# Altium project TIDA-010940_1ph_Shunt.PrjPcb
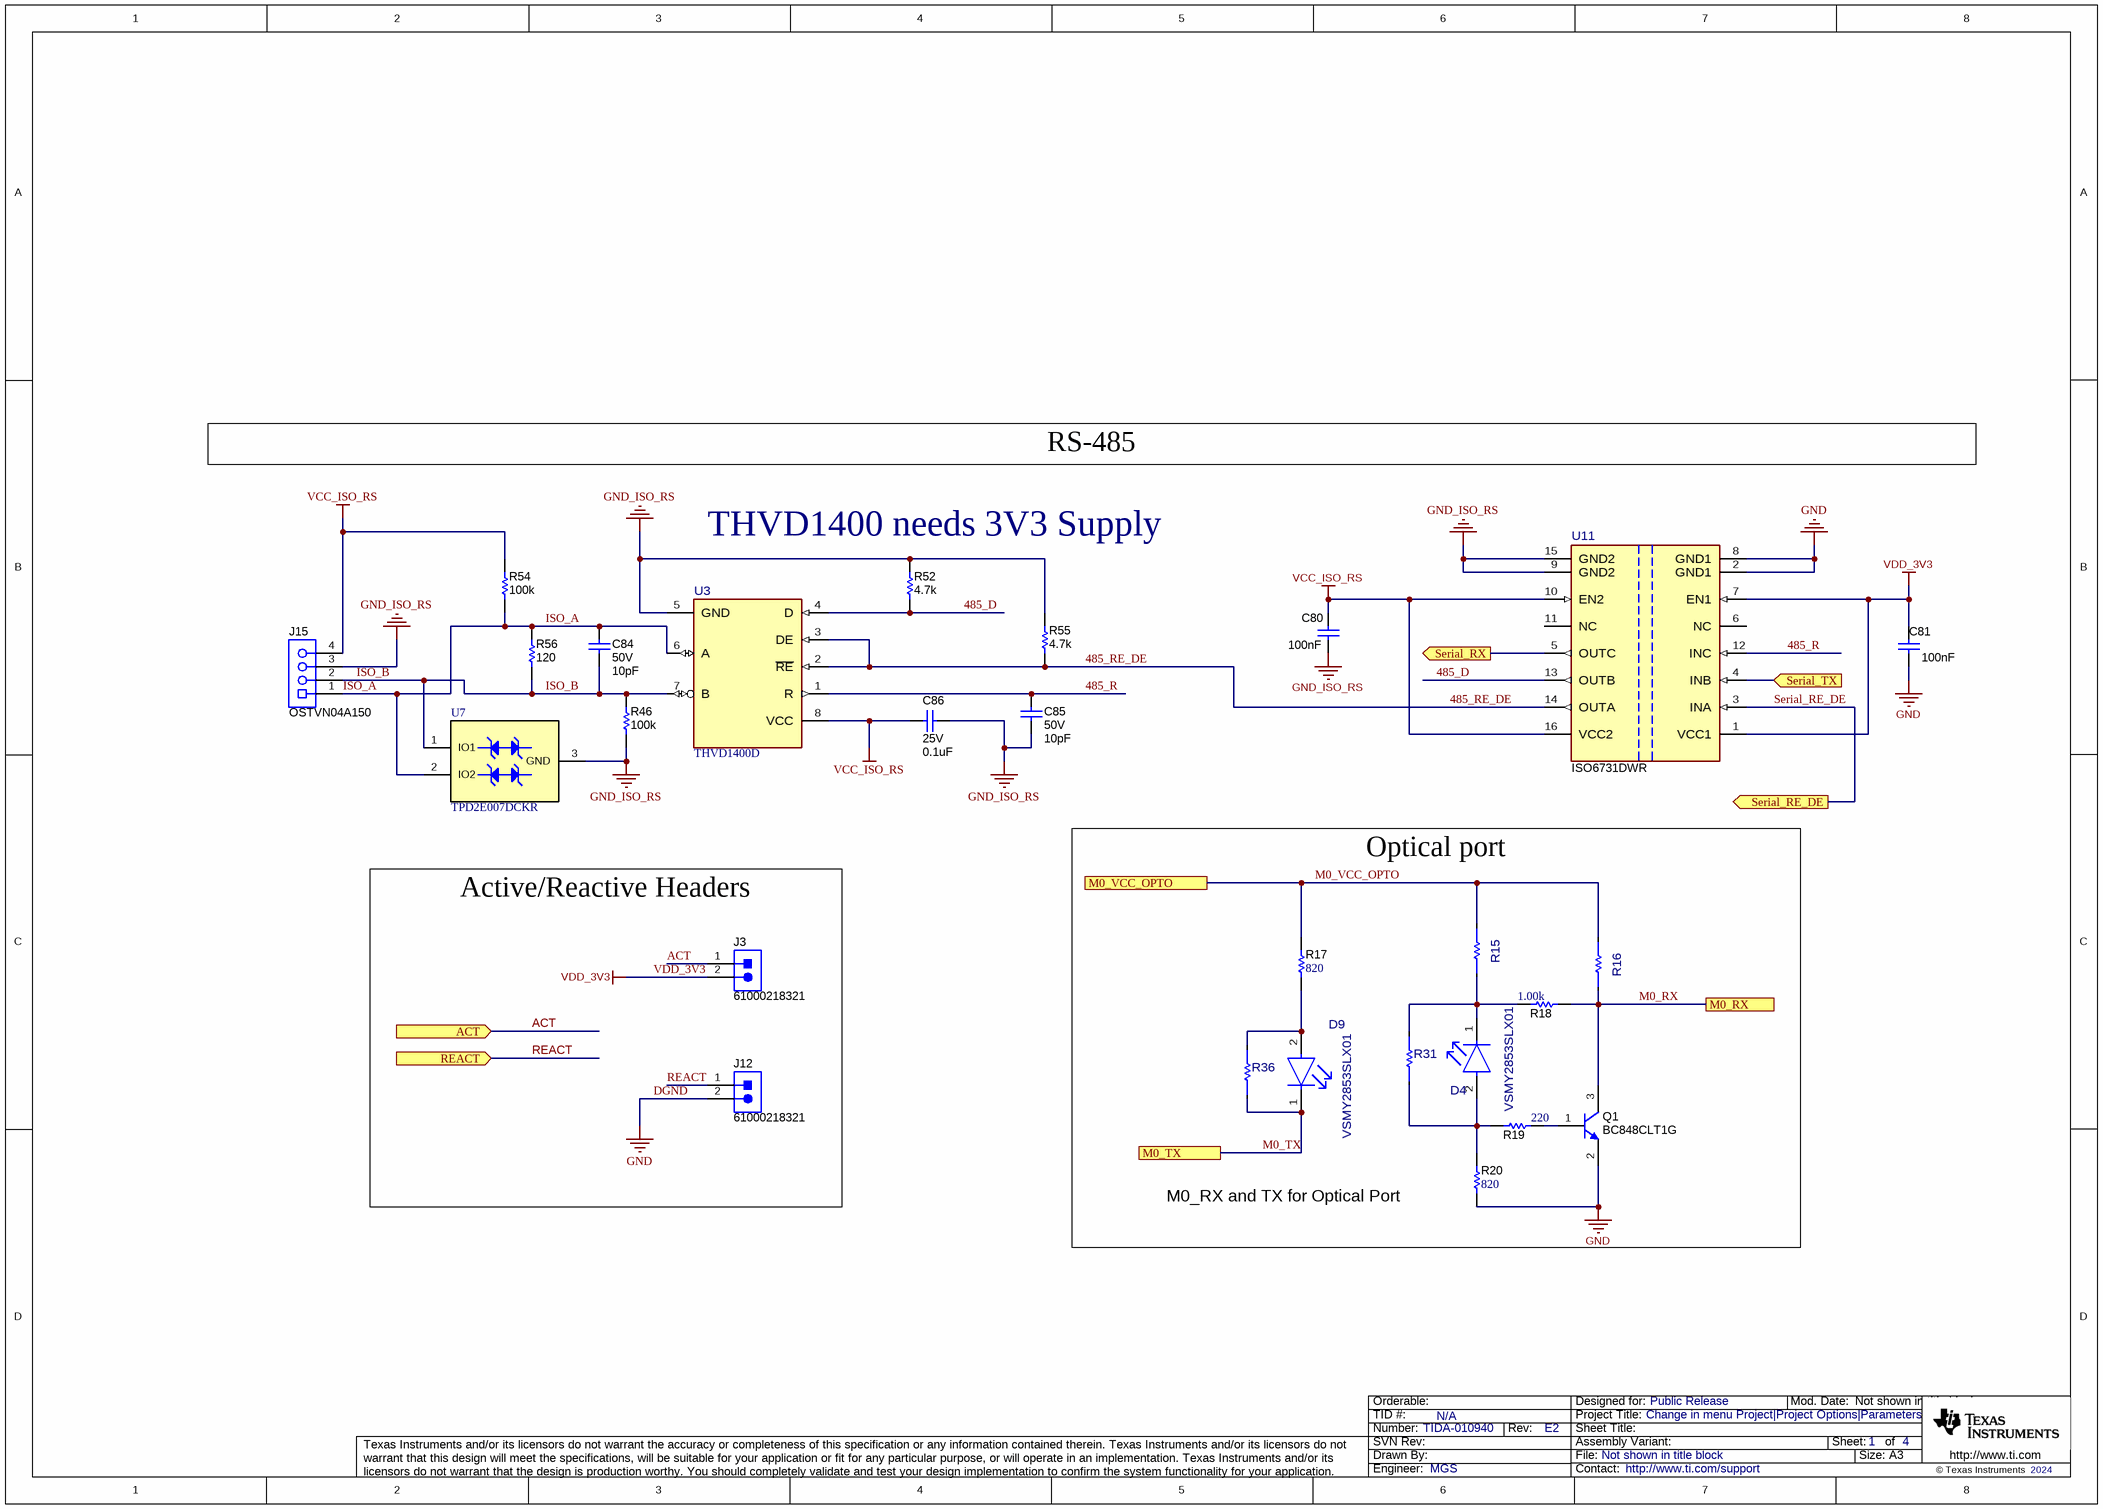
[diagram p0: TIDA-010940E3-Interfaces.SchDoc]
a0797195: Who did the Layout?; CopyrightYear: 2024; PCB_Rev: E3; PRJ_Customer: Public Release; PRJ_Engineer: MGS; PRJ_Number: TIDA-010940; PRJ_Title: Change in menu Project|Project Options|Parameters; SCH_Rev: E2; TechSupport: http://www.ti.com/support; TID: N/A
4 sheets, 137 parts. Net scope: global (net labels, ports and power ports of the same name join across sheets).
Board file: TIDA-010940E3.PcbDoc
Sheets:
  TIDA-010940E3-Interfaces.SchDoc
  TIDA-010940E3-Hardware.SchDoc
  TIDA-010940E3-1P_ADS131M03.SchDoc
  TIDA-010940E3-M0L228_80p.SchDoc

## Sheet TIDA-010940E3-Interfaces.SchDoc
size A3; Date: Not shown in title block; ApprovedBy: Not shown in title block; CheckedBy: Not shown in title block; Author: Not shown in title block; CompanyName: Not shown in title block; Engineer: Not shown in title block; Organization: Not shown in title block; Address1: Not shown in title block; Address2: Not shown in title block; Address3: Not shown in title block; Address4: Not shown in title block; DocumentNumber: 1; Revision: Use project parameter SCH_Rev; SheetNumber: 1; SheetTotal: 4; PageSetup: Record=PageOptions¦CenterHorizontal=True¦CenterVertical=True¦PrintScale=0.69¦XCorrection=1.00¦YCorrection=1.00¦PrintKind=0¦BorderSize=5000000¦LeftOffset=0¦BottomOffset=0¦Orientation=2¦PaperLength=1000¦PaperWidth=1000¦Scale=100¦PaperSource=15¦PrintQuality=600¦MediaType=1¦DitherType=10¦PaperKind=Letter¦PrintScaleMode=1

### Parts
C80  Cap_F: 100nF  [0603]  (hidden comment: C0603X104K3RACTU)
C81  Cap_F: 100nF  [0603]  (hidden comment: C0603X104K3RACTU)
C84  VDC_V: 50V  ValueDisplayed: 10pF  [0603]  (hidden comment: CGA3E2C0G1H100D080AA)
C85  VDC_V: 50V  ValueDisplayed: 10pF  [0603]  (hidden comment: CGA3E2C0G1H100D080AA)
C86  VDC_V: 25V  ValueDisplayed: 0.1uF  [0603]  (hidden comment: CGA3E2X8R1E104K080AA)
D4  VSMY2853SLX01  [FP-VSMY2853SLX01_SMT_LED_2MM30_2MM55-MFG]
D9  VSMY2853SLX01  [FP-VSMY2853SLX01_SMT_LED_2MM30_2MM55-MFG]
J3  61000218321  [Wurth_61000218321]
J12  61000218321  [Wurth_61000218321]
J15  OSTVN04A150  [On-Shore_OSTVN04A150]
Q1  BC848CLT1G  [SOT-23]
R15  CR0402-10W-000T  [FP-CR0402-10W-000T_0402-MFG]  (value not drawn)
R16  ERA-2ARB8061X  [FP-ERA-2ARB8061X_0402-MFG]  (value not drawn)
R17  ValueDisplayed: 820  [0402]  (hidden comment: RC0402FR-07820RL)
R18  ValueDisplayed: 1.00k  [0402]  (hidden comment: RC0402FR-071KL)
R19  ValueDisplayed: 220  [0402]  (hidden comment: ERJ-2RKF2200X)
R20  ValueDisplayed: 820  [0402]  (hidden comment: CRCW0402820RJNED)
R31  PMR18EZPJ000  [FP-PMR18EZPJ000_1206-MFG]  (value not drawn)
R36  PMR18EZPJ000  [FP-PMR18EZPJ000_1206-MFG]  (value not drawn)
R46  ValueDisplayed: 100k  [0603]  (hidden comment: CRCW0603100KJNEA)
R52  ValueDisplayed: 4.7k  [0603]  (hidden comment: CRCW06034K70JNEA)
R54  ValueDisplayed: 100k  [0603]  (hidden comment: CRCW0603100KJNEA)
R55  ValueDisplayed: 4.7k  [0603]  (hidden comment: CRCW06034K70JNEA)
R56  ValueDisplayed: 120  [0603]  (hidden comment: RT0603DRE07120RL)
U3  THVD1400D  [D0008B-MFG]
U7  TPD2E007DCKR  [DCK0003A_L]
U11  ISO6731DWR  [DW0016A-MFG]

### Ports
ACT (in), M0_RX, M0_TX, M0_VCC_OPTO, REACT (in), Serial_RE_DE (out), Serial_RX (out), Serial_TX (in)

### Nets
DGND: C81.2 J12.2 Q1.2(E) R20.1 U11.2(GND1) U11.8(GND1)  [also labelled GND]
GND_ISO_RS: C80.2 C85.1 C86.2 J15.3 R46.1 R52.2 R55.2 U3.5(GND) U7.3(GND) U11.9(GND2) U11.15(GND2)
VCC_ISO_RS: C80.1 C86.1 J15.4 R54.2 U3.8(VCC) U11.10(EN2) U11.16(VCC2)
VDD_3V3: C81.1 J3.2 U11.1(VCC1) U11.7(EN1)  [project net DVDD]
485_D: R52.1 U3.4(D) U11.13(OUTB)
485_R: C85.2 U3.1(R) U11.12(INC)
485_RE_DE: R55.1 U3.2(~{RE}) U3.3(DE) U11.14(OUTA)
ACT: J3.1 ; port ACT
ISO_A: C84.1 J15.1 R54.1 R56.2 U3.6(A) U7.2(IO2)
ISO_B: C84.2 J15.2 R46.2 R56.1 U3.7(B) U7.1(IO1)
M0_RX: Q1.3(C) R16.1 R18.1 ; port M0_RX
M0_TX: D9.1(Cathode) R36.1 ; port M0_TX
M0_VCC_OPTO: R15.2 R16.2 R17.2 ; port M0_VCC_OPTO
REACT: J12.1 ; port REACT
Serial_RE_DE: U11.3(INA) ; port Serial_RE_DE
Serial_RX: U11.5(OUTC) ; port Serial_RX
Serial_TX: U11.4(INB) ; port Serial_TX
NetD4_1: D4.1(Cathode) R15.1 R18.2 R31.2
NetD4_2: D4.2(Anode) R19.2 R20.2 R31.1
NetD9_2: D9.2(Anode) R17.1 R36.2
NetQ1_1: Q1.1(B) R19.1

Not connected (* = marked no-connect by the designer): U11 6(NC) 11(NC)

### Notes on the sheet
- RS-485
- (near R52) THVD1400 needs 3V3 Supply
- Active/Reactive Headers
- Optical port
- M0_RX and TX for Optical Port

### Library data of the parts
C80 C81 = CMP-0006979-5: CAP, CERM, 0.1 uF, 25 V, +/- 10%, X7R, 0603; Manufacturer: Kemet; TaMin_C: -55°C; Polarized: N; SizeAreaWB_mm2: 4.68; Value1: Unknown; U/M: EA; Value: 0.1uF; TaMax_C: 125°C; SizeZ_mm: 1; SizeX_mm: 1.6; SizeY_mm: 0.8; Value2: 25V; SizeArea_mm2: 1.28; AEC Category: Q200
C84 C85 = CMP-0007069-4: CAP, CERM, 10 pF, 50 V, +/- 5%, C0G/NP0, AEC-Q200 Grade 1, 0603; Manufacturer: TDK; TaMin_C: -55°C; Polarized: N; SizeAreaWB_mm2: 4.68; Value1: Unknown; U/M: EA; Value: 10pF; TaMax_C: 125°C; SizeZ_mm: 1; SizeX_mm: 1.6; SizeY_mm: 0.8; SizeArea_mm2: 1.28; AEC Qualified: Y; AEC Category: Q200
C86 = CMP-0007090-4: CAP, CERM, 0.1 uF, 25 V, +/- 10%, X8R, AEC-Q200 Grade 0, 0603; Manufacturer: TDK; TaMin_C: -55°C; Polarized: N; SizeAreaWB_mm2: 4.68; Value1: Unknown; U/M: EA; Value: 0.1uF; TaMax_C: 150°C; SizeZ_mm: 1; SizeX_mm: 1.6; SizeY_mm: 0.8; SizeArea_mm2: 1.28; CompType: Capacitor; AEC Qualified: Y; Cap_F: 100nF; AEC Grade: 0; AEC Category: Q200
D4 D9 = CMP-0120648-1: IR Emitter High Speed 850nm 50mW/sr 100mA 1.9V 2-Pin SMD T/R; Manufacturer: Vishay; Color: Infrared; Tjmax_C: 100°C; Vf_V: 1.6V; Angle: 56°; Power_TotalModule: 190mW; SizeZ_mm: 2.5mm; Vr_V: 5V; AEC Grade: Grade 3; AEC Qualified: Yes; Led Orientation: Side View; TaMax_C: +85°C; TaMin_C: -40°C
J3 J12 = CMP-0054787-1: Header, 2.54mm, 2x1, Gold, SMT; Manufacturer: Wurth Elektronik; CNHeader: TRUE; Shrouded: N; Gender: Male; Row_Count: 1; Pitch_mm: 2.54; CT: FALSE
J15 = CMP-0075095-1: Terminal Block, 2.54mm, 4x1, Brass, TH; Manufacturer: On-Shore Technology; CT: True; CNHeader: False
Q1 = CMP-0000377-2: Transistor, NPN, 30 V, 0.1 A, SOT-23; Manufacturer: ON Semiconductor; TaMax_C: 150°C; Value2: 800; Value1: 0.1 A; Vcesat1_V: 700mV; SizeX_mm: 2.5; SizeY_mm: 3; TaMin_C: -55°C; IcRated_A: 100mA; CompType: BJT; SizeZ_mm: 1.1; Value: 30 V; SizeArea_mm2: 7.5; NPN: 1; Vceo_V: 30V; PNP: 0; AEC Category: Q101; SizeAreaWB_mm2: 14; U/M: EA
R15 = CMP-0094948-1: 0 Ohms Jumper 0.1W, 1/10W Chip Resistor 0402 (1005 Metric) - Thick Film; Manufacturer: Venkel; Value: 0uΩ; Res_ohm: 0; SizeZ_mm: 0.4mm; AEC Qualified: No; VDC_V: 50V; Power_W: 100mW
R16 = CMP-0121809-1: 8.06 kOhms ±0.1% 0.063W, 1/16W Chip Resistor 0402 (1005 Metric) Automotive AEC-Q200 Thin Film; Manufacturer: Panasonic; Power_W: 63mW; TempCo: 10ppm/°C; Value: 8.06k; SizeZ_mm: 0.4mm; AEC Qualified: Yes; VDC_V: 50V; AEC Grade: Grade 1
R17 = CMP-0026743-1: RES, 820, 1%, 0.063 W, 0402; Manufacturer: Yageo America; Power_W: 63mW; TempCo: 100 ppm/C; Value_Code: 820R; Value: 820; SizeX_mm: 1; SizeY_mm: 0.5; SizeZ_mm: 0.6; Value2: 0.063W; AEC Qualified: N; VDC_V: 50V; AEC Category: Q200; U/M: EA
R18 = CMP-0026725-1: RES, 1.00 k, 1%, 0.0625 W, 0402; Manufacturer: Yageo America; Power_W: 62.5mW; TempCo: 100 ppm/C; Value_Code: 1k00; Value: 1.00k; EIA_Code: E96; Res_ohm: 1k; SizeX_mm: 1; SizeY_mm: 0.5; SizeZ_mm: 0.6; AEC Qualified: N; VDC_V: 50V; AEC Category: Q200; U/M: EA
R19 = CMP-0026680-1: RES, 220, 1%, 0.1 W, AEC-Q200 Grade 0, 0402; Manufacturer: Panasonic; Power_W: 100mW; TempCo: 100 ppm/C; Value_Code: 220R; Value: 220; SizeX_mm: 1; SizeY_mm: 0.5; SizeZ_mm: 0.6; Value2: 0.1W; AEC Qualified: Y; VDC_V: 50V; AEC Category: Q200; AEC Grade: 0; U/M: EA
R20 = CMP-0026979-3: RES, 820, 5%, 0.063 W, AEC-Q200 Grade 0, 0402; Manufacturer: Vishay-Dale; Power_W: 63mW; TempCo: 200 ppm/C; Value_Code: 820R; Value: 820; EIA_Code: E24; SizeX_mm: 1; SizeY_mm: 0.5; SizeZ_mm: 0.6; Value2: 0.063W; AEC Qualified: Y; VDC_V: 50V; AEC Category: Q200; AEC Grade: 0
R31 R36 = CMP-0093507-1: 0 Ohms Jumper 1W Chip Resistor 1206 (3216 Metric) Automotive AEC-Q200, Current Sense Thick Film; Manufacturer: Rohm Semiconductor; SizeZ_mm: 0.42mm; AEC Grade: Grade 0; Value: 0; AEC Qualified: Yes; Max Current: 38.7A
R46 R54 = CMP-0025698-4: RES, 100 k, 5%, 0.1 W, AEC-Q200 Grade 0, 0603; Manufacturer: Vishay-Dale; Power_W: 100mW; TempCo: 200 ppm/C; Value: 100k; EIA_Code: E24; SizeX_mm: 1.6; SizeY_mm: 0.8; SizeZ_mm: 1; Value2: 0.1W; SizeArea_mm2: 1.28; AEC Qualified: Y; VDC_V: 75V; AEC Category: Q200; AEC Grade: 0
R52 R55 = CMP-0025817-4: RES, 4.7 k, 5%, 0.1 W, AEC-Q200 Grade 0, 0603; Manufacturer: Vishay-Dale; Power_W: 100mW; TempCo: 200 ppm/C; Value_Code: 4k70; Value: 4.7k; EIA_Code: E24; SizeX_mm: 1.6; SizeY_mm: 0.8; SizeZ_mm: 1; Value2: 0.1W; SizeArea_mm2: 1.28; AEC Qualified: Y; VDC_V: 75V; AEC Category: Q200; AEC Grade: 0
R56 = CMP-0024624-2: RES, 120, 0.5%, 0.1 W, 0603; Manufacturer: Yageo America; Power_W: 100mW; TempCo: 50 ppm/C; Value_Code: 120R; U/M: EA; Value: 120; EIA_Code: E192; SizeX_mm: 1.6; SizeY_mm: 0.8; SizeZ_mm: 1; Value2: 0.1W; SizeArea_mm2: 1.28; VDC_V: 75V; AEC Category: Q200
U3 = CMP-0089978-1: 500 kbps RS-485 Transceivers With ±8-kV IEC ESD Protection; Manufacturer: Texas Instruments; Interface: RS-485,RS-422; SizeZ_mm: 1.75mm; Number Of Receivers: 1; TaMax_C: +125°C; TJmax_C: +150°C; Min Supply Voltage: 4.5V; Nominal Supply Current: 275-440uA; Simplex Duplex: Half-Duplex; Standoff Height: 0.11mm; Max Supply Voltage: 5.5V; TaMin_C: -40°C; Data Rate: 500kbits/s; AEC Qualified: No
U7 = CMP-0043100-2: ESD Protection Array for AC Signal Data Interface, 2 Channels, -40 to +85 degC, 3-pin SC70 (DCK), Green (RoHS & no Sb/Br); Manufacturer: Texas Instruments; IO Leakage Current(nA): 50; IEC 61000-4-2 Contact(+/- kV): 8; IO Capacitance(Typ)(pF): 15; Breakdown Voltage(Min)(V): +/-14; SubFamily: ESD Solution; AEC Category: Q200; AEC Qualified: N; CompType: IC; SizeAreaWB_mm2: 9.3; SizeArea_mm2: 4.2; SizeX_mm: 2.1; SizeY_mm: 2; SizeZ_mm: 1.1
U11 = CMP-0094636-1: Manufacturer: Texas Instruments; Min Supply Voltage: 1.71V; TJmax_C: +150°C; Max Supply Voltage: 5.5V; Standoff Height: 0.1mm; TaMax_C: +125°C; SizeZ_mm: 2.65mm; Interface: SPI,CAN,RS-232,RS-485; TaMin_C: -40°C; AEC Qualified: No

## Sheet TIDA-010940E3-Hardware.SchDoc
size 431 x 279 mm; Date: Not shown in title block; ApprovedBy: Not shown in title block; CheckedBy: Not shown in title block; Author: Not shown in title block; CompanyName: Not shown in title block; Engineer: Not shown in title block; Organization: Not shown in title block; Address1: Not shown in title block; Address2: Not shown in title block; Address3: Not shown in title block; Address4: Not shown in title block; DocumentNumber: 3; Revision: Use project parameter SCH_Rev; SheetNumber: 2; SheetTotal: 4; PageSetup: Record=PageOptions¦CenterHorizontal=True¦CenterVertical=True¦PrintScale=1.00¦XCorrection=1.00¦YCorrection=1.00¦PrintKind=0¦BorderSize=5000000¦LeftOffset=0¦BottomOffset=0¦Orientation=2¦PaperLength=1000¦PaperWidth=1000¦Scale=100¦PaperSource=15¦PrintQuality=600¦MediaType=1¦DitherType=10¦PaperKind=Letter¦PrintScaleMode=1
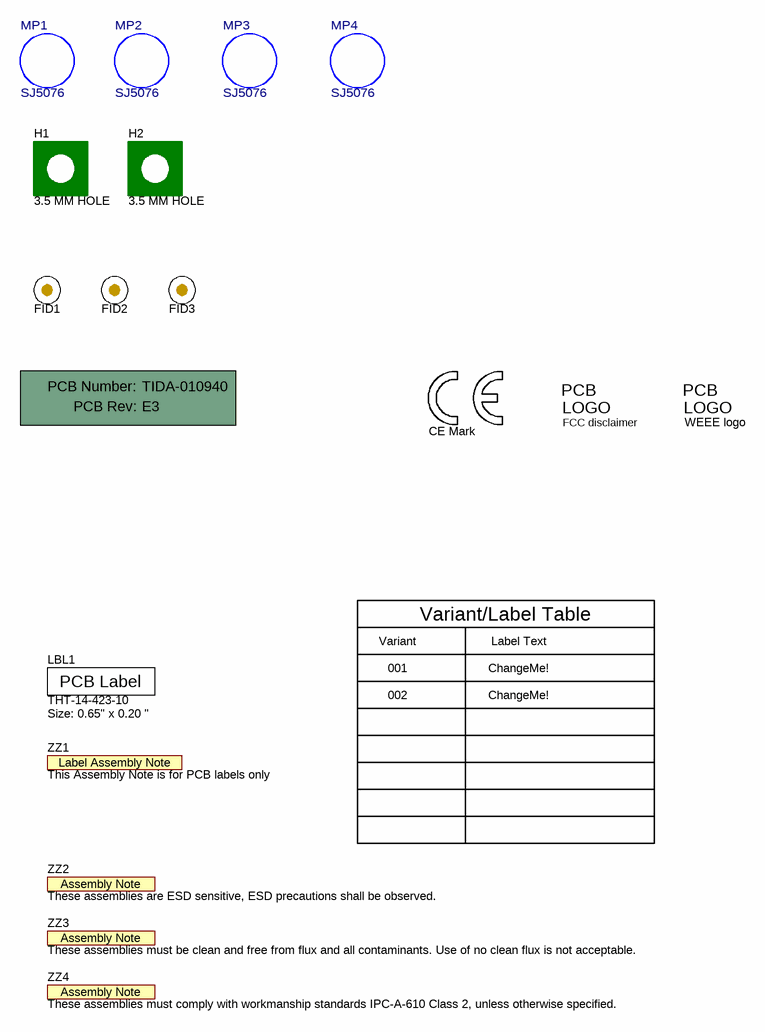
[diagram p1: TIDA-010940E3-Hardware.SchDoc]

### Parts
!PCB  Printed Circuit Board  (value not drawn)  (mechanical)
FID1  Fiducial  [Fiducial10-20]  (value not drawn)
FID2  Fiducial  [Fiducial10-20]  (value not drawn)
FID3  Fiducial  [Fiducial10-20]  (value not drawn)
H1  3.5 MM HOLE  [3_5MM_HOLE]
H2  3.5 MM HOLE  [3_5MM_HOLE]
LBL1  THT-14-423-10  Note: Size: 0.65" x 0.20 "  [Label_650x200]
Logo2  CE Mark  [CE_Mark_5mm]  (no BOM)
Logo3  FCC disclaimer  [FCC_disclaimer]  (no BOM)
Logo4  WEEE logo  [WEEE_Minimum]  (no BOM)
MP1  SJ5076  [FP-SJ5076_BUMPER_CYLIN-MFG]
MP2  SJ5076  [FP-SJ5076_BUMPER_CYLIN-MFG]
MP3  SJ5076  [FP-SJ5076_BUMPER_CYLIN-MFG]
MP4  SJ5076  [FP-SJ5076_BUMPER_CYLIN-MFG]
ZZ1  This Assembly Note is for PCB labels only  [AssemblyNoteLabel]  (no BOM)
ZZ2  These assemblies are ESD sensitive, ESD precautions shall be observed.  [AssemblyNote]  (no BOM)
ZZ3  These assemblies must be clean and free from flux and all contaminants. Use of no clean flux is not acceptable.  [AssemblyNote]  (no BOM)
ZZ4  These assemblies must comply with workmanship standards IPC-A-610 Class 2, unless otherwise specified.  [AssemblyNote]  (no BOM)

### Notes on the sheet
- Variant
- Variant/Label Table
- Label Text
- 001
- 002
- ChangeMe!

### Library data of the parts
!PCB = CMP-0003618-2: Manufacturer: Any; PartNumber: TIDA-010940
FID1-FID3 = CMP-0077181-1: Fiducial mark.  There is nothing to buy or mount.
H1 H2 = CMP-0079299-1: 3.5 mm PCB Hole; Manufacturer: Any; CompType: Pad
LBL1 = CMP-0003625-1: Thermal Transfer Printable Labels, 0.650" W x 0.200" H - 10,000 per roll; Manufacturer: Brady; CompType: Label
Logo2 = CMP-0074844-1: SymbolCreator: a0412235
Logo3 = CMP-0074847-1: FCC_disclaimer; Library Reference: Logo
Logo4 = CMP-0074769-1
MP1-MP4 = CMP-0097139-1: Bumper Cylindrical, Flat Top 0.315" Dia (8.00mm) Polyurethane Black; Manufacturer: 3M; SizeZ_mm: 3.3mm; AEC Qualified: No
ZZ1 = CMP-0003616-3
ZZ2 = CMP-0077236-1
ZZ3 = CMP-0077237-1
ZZ4 = CMP-0077238-1

## Sheet TIDA-010940E3-1P_ADS131M03.SchDoc
size 431 x 279 mm; Date: Not shown in title block; ApprovedBy: Not shown in title block; CheckedBy: Not shown in title block; Author: Not shown in title block; CompanyName: Not shown in title block; Engineer: Not shown in title block; Organization: Not shown in title block; Address1: Not shown in title block; Address2: Not shown in title block; Address3: Not shown in title block; Address4: Not shown in title block; DocumentNumber: 2; Revision: Use project parameter SCH_Rev; SheetNumber: 3; SheetTotal: 4; PageSetup: Record=PageOptions¦CenterHorizontal=True¦CenterVertical=True¦PrintScale=1.00¦XCorrection=1.00¦YCorrection=1.00¦PrintKind=0¦BorderSize=5000000¦LeftOffset=0¦BottomOffset=0¦Orientation=2¦PaperLength=1000¦PaperWidth=1000¦Scale=100¦PaperSource=15¦PrintQuality=600¦MediaType=1¦DitherType=10¦PaperKind=Letter¦PrintScaleMode=1
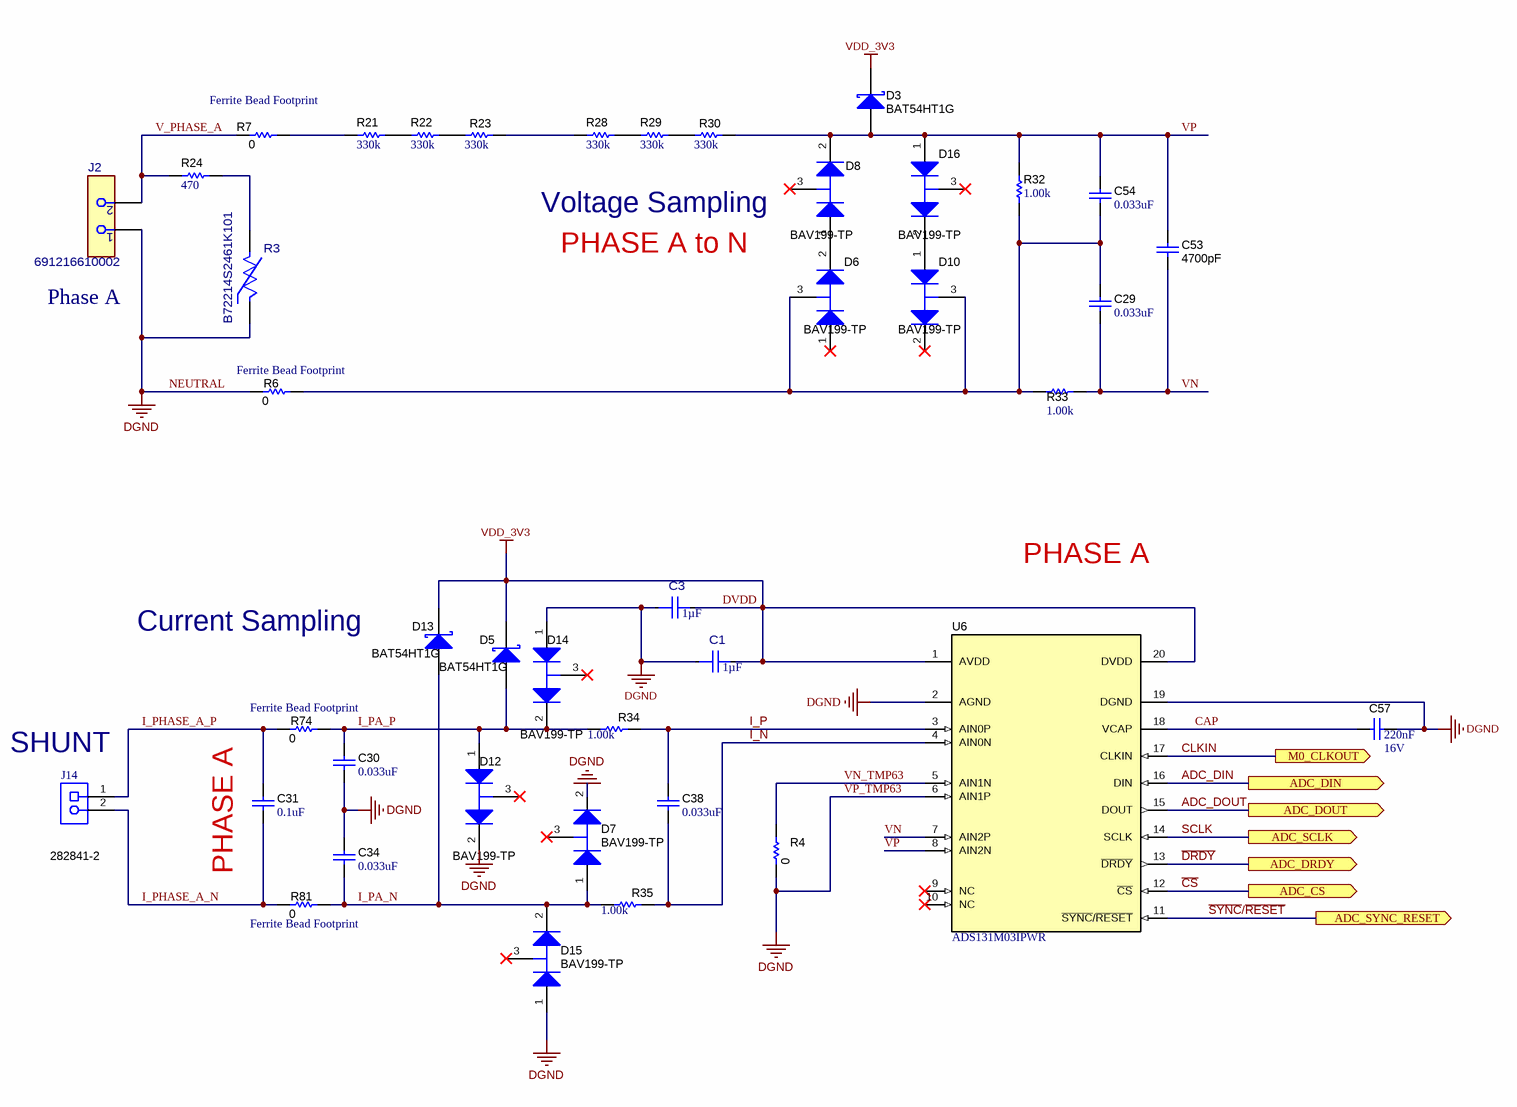
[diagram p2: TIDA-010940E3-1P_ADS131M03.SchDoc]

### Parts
C1  Cap_F: 1µF  [FP-GMC04X7R105K10NT_0402-MFG]  (hidden comment: GMC04X7R105K10NT)
C3  Cap_F: 1µF  [FP-GMC04X7R105K10NT_0402-MFG]  (hidden comment: GMC04X7R105K10NT)
C29  ValueDisplayed: 0.033uF  [0603]  (hidden comment: GRM188R71C333KA01D)
C30  ValueDisplayed: 0.033uF  [0603]  (hidden comment: GRM188R71C333KA01D)
C31  ValueDisplayed: 0.1uF  [0603]  (hidden comment: 06035C104KAT2A)
C34  ValueDisplayed: 0.033uF  [0603]  (hidden comment: GRM188R71C333KA01D)
C38  ValueDisplayed: 0.033uF  [0603]  (hidden comment: GRM188R71C333KA01D)
C53  ValueDisplayed: 4700pF  [0603]  (hidden comment: C0603C472J1GAC7867)
C54  ValueDisplayed: 0.033uF  [0603]  (hidden comment: GRM188R71C333KA01D)
C57  Cap_F: 220nF  VDC_V: 16V  [0402]  (hidden comment: CL05B224KO5NNNC)
D3  BAT54HT1G  [SOD-323]
D5  BAT54HT1G  [SOD-323]
D6  BAV199-TP  [SOT-23L]
D7  BAV199-TP  [SOT-23L]
D8  BAV199-TP  [SOT-23L]
D10  BAV199-TP  [SOT-23L]
D12  BAV199-TP  [SOT-23L]
D13  BAT54HT1G  [SOD-323]
D14  BAV199-TP  [SOT-23L]
D15  BAV199-TP  [SOT-23L]
D16  BAV199-TP  [SOT-23L]
J2  691216610002  [FP-691216610002_TERM_BLK_2-MFG]
J14  282841-2  [TEC_282841-2]
R3  B72214S2461K101  [FP-B72214S2461K101_RADIAL-MFG]
R4  ValueDisplayed: 0  [0603]  (hidden comment: ERJ-3GEY0R00V)
R6  ValueDisplayed: 0  [0603]  (hidden comment: ERJ-3GEY0R00V)
R7  ValueDisplayed: 0  [0603]  (hidden comment: ERJ-3GEY0R00V)
R21  ValueDisplayed: 330k  [TNPV1206]  (hidden comment: TNPV1206330KBEEN)
R22  ValueDisplayed: 330k  [TNPV1206]  (hidden comment: TNPV1206330KBEEN)
R23  ValueDisplayed: 330k  [TNPV1206]  (hidden comment: TNPV1206330KBEEN)
R24  ValueDisplayed: 470  [AC05_Vert]  (hidden comment: AC05000004700JAC00)
R28  ValueDisplayed: 330k  [TNPV1206]  (hidden comment: TNPV1206330KBEEN)
R29  ValueDisplayed: 330k  [TNPV1206]  (hidden comment: TNPV1206330KBEEN)
R30  ValueDisplayed: 330k  [TNPV1206]  (hidden comment: TNPV1206330KBEEN)
R32  ValueDisplayed: 1.00k  [0603]  (hidden comment: RC0603FR-071KL)
R33  ValueDisplayed: 1.00k  [0603]  (hidden comment: RC0603FR-071KL)
R34  ValueDisplayed: 1.00k  [0603M]  (hidden comment: RC0603FR-071KL)
R35  ValueDisplayed: 1.00k  [0603M]  (hidden comment: RC0603FR-071KL)
R74  ValueDisplayed: 0  [0603]  (hidden comment: ERJ-3GEY0R00V)
R81  ValueDisplayed: 0  [0603]  (hidden comment: ERJ-3GEY0R00V)
U6  ADS131M03IPWR  [PW0020A_N]

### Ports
ADC_CS (out), ADC_DIN (out), ADC_DOUT (out), ADC_DRDY (out), ADC_SCLK (out), ADC_SYNC_RESET (out), M0_CLKOUT (out)

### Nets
DGND: C1.1 C3.1 C30.2 C34.1 C57.1 D7.2(K) D12.2(K) D14.1(A) D15.1(A) J2.1 R3.2 R4.1 R6.1 U6.2(AGND) U6.6(AIN1P) U6.19(DGND)  [also labelled NEUTRAL, VP_TMP63]
DVDD: C1.2 C3.2 D3.1(K) D5.1(K) D13.1(K) U6.1(AVDD) U6.20(DVDD)  [also labelled VDD_3V3]
ADC_DIN: U6.16(DIN) ; port ADC_DIN
ADC_DOUT: U6.15(DOUT) ; port ADC_DOUT
~{CS}: U6.12(~{CS}) ; port ADC_CS  [project net ADC_SPI0_CS1]
CAP: C57.2 U6.18(VCAP)
CLKIN: U6.17(CLKIN) ; port M0_CLKOUT
~{DRDY}: U6.13(~{DRDY}) ; port ADC_DRDY
I_N: C38.2 R35.2 U6.4(AIN0N)
I_P: C38.1 R34.2 U6.3(AIN0P)
I_PA_N: C34.2 D7.1(A) D13.2(A) D15.2(K) R35.1 R81.2
I_PA_P: C30.1 D5.2(A) D12.1(A) D14.2(K) R34.1 R74.2
I_PHASE_A_N: C31.2 J14.2 R81.1
I_PHASE_A_P: C31.1 J14.1 R74.1
~{SYNC}/~{RESET}: U6.11(~{SYNC}/~{RESET}) ; port ADC_SYNC_RESET
SCLK: U6.14(SCLK) ; port ADC_SCLK  [project net ADC_SPI0_SCLK]
V_PHASE_A: J2.2 R7.1 R24.1
VN: C29.2 C53.2 R33.2 U6.7(AIN2P)
VN_TMP63: R4.2 U6.5(AIN1N)
VP: C53.1 C54.1 D3.2(A) D8.2(K) D16.1(A) R30.2 R32.2 U6.8(AIN2N)
NetC29_1: C29.1 C54.2 D6.3(C) D10.3(C) R6.2 R32.1 R33.1
NetD6_2: D6.2(K) D8.1(A)
NetD10_1: D10.1(A) D16.2(K)
NetR3_1: R3.1 R24.2
NetR7_2: R7.2 R21.2
NetR21_1: R21.1 R22.2
NetR22_1: R22.1 R23.1
NetR23_2: R23.2 R28.2
NetR28_1: R28.1 R29.2
NetR29_1: R29.1 R30.1

Not connected (* = marked no-connect by the designer): D6 1(A)*; D7 3(C)*; D8 3(C)*; D10 2(K)*; D12 3(C)*; D14 3(C)*; D15 3(C)*; D16 3(C)*; U6 9(NC)* 10(NC)*

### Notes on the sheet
- Ferrite Bead Footprint
- Voltage Sampling
- PHASE A to N
- Phase A
- (near R6) Ferrite Bead Footprint
- PHASE A
- Current Sampling
- (near J14) SHUNT
- (near R74) Ferrite Bead Footprint
- (near C31) PHASE A
- (near R81) Ferrite Bead Footprint

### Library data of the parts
C1 C3 = CMP-0093200-1: 1µF ±10% 10V Ceramic Capacitor X7R 0402 (1005 Metric); Manufacturer: Cal-Chip Electronics; TempCo: 15%; SizeZ_mm: 0.6mm; AEC Qualified: No; ValueDisplayed: 1uF
C29 C30 C34 C38 C54 = CMP-0007392-5: CAP, CERM, 0.033 uF, 16 V, +/- 10%, X7R, 0603; Manufacturer: MuRata; TaMin_C: -55°C; Polarized: N; SizeAreaWB_mm2: 4.68; Value1: Unknown; U/M: EA; TaMax_C: 125°C; SizeZ_mm: 1; SizeX_mm: 1.6; SizeY_mm: 0.8; Value2: 16V; SizeArea_mm2: 1.28; Cap_F: 33nF; AEC Category: Q200
C31 = CMP-0006802-4: CAP, CERM, 0.1 uF, 50 V, +/- 10%, X7R, 0603; Manufacturer: AVX; TaMin_C: -55°C; Polarized: N; SizeAreaWB_mm2: 4.68; Value1: Unknown; U/M: EA; Value: 0.1uF; TaMax_C: 125°C; SizeZ_mm: 1; SizeX_mm: 1.6; SizeY_mm: 0.8; Value2: 50V; SizeArea_mm2: 1.28; Cap_F: 100nF; AEC Category: Q200
C53 = CMP-0006941-4: CAP, CERM, 4700 pF, 100 V, +/- 5%, C0G/NP0, 0603; Manufacturer: Kemet; TaMin_C: -55°C; Polarized: N; SizeAreaWB_mm2: 4.68; Value1: Unknown; U/M: EA; Value: 4700pF; TaMax_C: 125°C; SizeZ_mm: 1; SizeX_mm: 1.6; SizeY_mm: 0.8; Value2: 100V; SizeArea_mm2: 1.28; Cap_F: 4.7nF; AEC Category: Q200
C57 = CMP-0860563-1: CAP, CERM, 0.22 µF, 16 V,+/- 10%, X7R, 0402; Manufacturer: Samsung Electro-Mechanics; SizeZ_mm: 0.6; AEC Qualified: N; SizeX_mm: 1; Green_REACh: Incomplete; TaMin_C: -55°C; SizeArea_mm2: 0.5; TaMax_C: 125°C; U/M: EA; Green_Lifecycle: Active; SizeAreaWB_mm2: 3; AEC Category: Q200; Value: 0.22uF
D3 D5 D13 = CMP-0028455-2: Diode, Schottky, 30 V, 0.2 A, SOD-323; Manufacturer: ON Semiconductor; Vr_V: 30V; Value: 30V; SizeZ_mm: 1; Value1: 0.2A; SizeAreaWB_mm2: 8.695; Vf_V: 350mV; Io_A: 200mA; SizeX_mm: 2.7; SizeY_mm: 1.35; Green_Lifecycle: Active; AEC Category: Q101; Value2: 0.35V; SizeArea_mm2: 3.645; Green_REACh: Passed
D6-D8 D10 D12 D14-D16 = CMP-0076968-2: Diode, Switching, 70 V, 0.215 A, SOT-23; Manufacturer: Micro Commercial Components; SizeZ_mm: 1.1; Vr_V: 70V; Value1: 0.215A; SizeArea_mm2: 7.5; TJmax_C: 150°C; SizeY_mm: 3.0; AEC Category: Q101; SizeAreaWB_mm2: 14.0; Io_A: 215mA; Value: 70V; SizeX_mm: 2.5; Green_Lifecycle: Not Set; Green_REACh: Incomplete
J2 = CMP-0109233-1: 2 Position Wire to Board Terminal Block Horizontal with Board 0.400" (10.16mm) Through Hole; Manufacturer: Wurth Electronics; Current_A: 14A; Max Wire Gauge: 12; SizeZ_mm: 13.9mm; Conn Gender: Female; Min Wire Gauge: 30; Is Female: yes; Row_Count: 1; AEC Qualified: No; ContactFinish: Nickel; Voltage_V: 300V
J14 = CMP-0054973-1: Terminal Block, 2x1, 5.08mm, TH; Manufacturer: TE Connectivity; CNHeader: FALSE; Green_Lifecycle: Active; Green_REACh: Passed; CT: TRUE
R3 = CMP-0049856-1: Var MOV 460VAC/615VDC 5000A 750V Thru-Hole Radial Bulk; Manufacturer: TDK; SizeZ_mm: 19mm; AEC Qualified: No; Cap_F: 260pF; Clamping Voltage: 1240V; Vc: 50A; VDC_V: 615V; Voltage Tolerance: 10%
R4 R6 R7 R74 R81 = CMP-0025874-4: RES, 0, 5%, 0.1 W, AEC-Q200 Grade 0, 0603; Manufacturer: Panasonic; Power_W: 100mW; TempCo: 600 ppm/C; Value_Code: 0000; Value: 0; EIA_Code: E24; SizeX_mm: 1.6; SizeY_mm: 0.8; SizeZ_mm: 1; Value2: 0.1W; SizeArea_mm2: 1.28; AEC Qualified: Y; VDC_V: 50V; AEC Category: Q200; SizeAreaWB_mm2: 4.68
R21-R23 R28-R30 = CMP-0018811-2: RES, 330 k, 0.1%, 1 W, 1206; Manufacturer: Vishay Draloric; Power_W: 1W; TempCo: 25 ppm/C; U/M: EA; Value: 330k; SizeX_mm: 3.2; SizeY_mm: 1.6; SizeZ_mm: 0.65; SizeArea_mm2: 5.12; AEC Qualified: N; VDC_V: 700V; AEC Category: Q200
R24 = CMP-0085526-3: RES, 470, 5%, 5 W, AEC-Q200 Grade 0, Dia 7.5mm; Manufacturer: Vishay-Bccomponents; Value: 470; Value_Code: 470R; SizeZ_mm: 7.5; AEC Grade: 0; EIA_Code: E24; AEC Category: Q200; SizeX_mm: 28; Value2: 5W; SizeArea_mm2: 210; SizeAreaWB_mm2: 285; AEC Qualified: Y
R32 = CMP-0022895-5: RES, 1.00 k, 1%, 0.1 W, 0603; Manufacturer: Yageo; Power_W: 100mW; TempCo: 100 ppm/C; Value_Code: 1k00; Value: 1.00k; EIA_Code: E96; Res_ohm: 1k; SizeX_mm: 1.6; SizeY_mm: 0.8; SizeZ_mm: 1; Value2: 0.1W; SizeArea_mm2: 1.28; AEC Qualified: N; VDC_V: 75V; AEC Category: Q200; SizeAreaWB_mm2: 4.68
R33-R35 = CMP-0022895-5: RES, 1.00 k, 1%, 0.1 W, 0603; Manufacturer: Yageo; Power_W: 100mW; TempCo: 100 ppm/C; Value: 1.00k; Res_ohm: 1k; SizeZ_mm: 1; AEC Qualified: N; VDC_V: 75V; Value_Code: 1k00; EIA_Code: E96; SizeX_mm: 1.6; SizeY_mm: 0.8; Value2: 0.1W; SizeArea_mm2: 1.28; AEC Category: Q200; SizeAreaWB_mm2: 4.68
U6 = CMP-0080543-1: 3-Channel, 24-Bit, Simultaneously-Sampling, Delta-Sigma ADC, PW0020A (TSSOP-20); Alternate PartNumber: ADS131M03IPWT; Alternate Manufacturer: Texas Instruments; SizeAreaWB_mm2: 73.96; SizeZ_mm: 1.2; SizeX_mm: 6.6; SizeArea_mm2: 43.56; CompType: IC; AEC Qualified: N; AEC Category: Q200

## Sheet TIDA-010940E3-M0L228_80p.SchDoc
size A2; Date: Not shown in title block; ApprovedBy: Not shown in title block; CheckedBy: Not shown in title block; Author: Not shown in title block; CompanyName: Not shown in title block; Engineer: Not shown in title block; Organization: Not shown in title block; Address1: Not shown in title block; Address2: Not shown in title block; Address3: Not shown in title block; Address4: Not shown in title block; DocumentNumber: 1; Revision: Use project parameter SCH_Rev; SheetNumber: 4; SheetTotal: 4; PageSetup: Record=PageOptions¦CenterHorizontal=True¦CenterVertical=True¦PrintScale=0.69¦XCorrection=1.00¦YCorrection=1.00¦PrintKind=0¦BorderSize=5000000¦LeftOffset=0¦BottomOffset=0¦Orientation=2¦PaperLength=1000¦PaperWidth=1000¦Scale=100¦PaperSource=15¦PrintQuality=600¦MediaType=1¦DitherType=10¦PaperKind=Letter¦PrintScaleMode=1
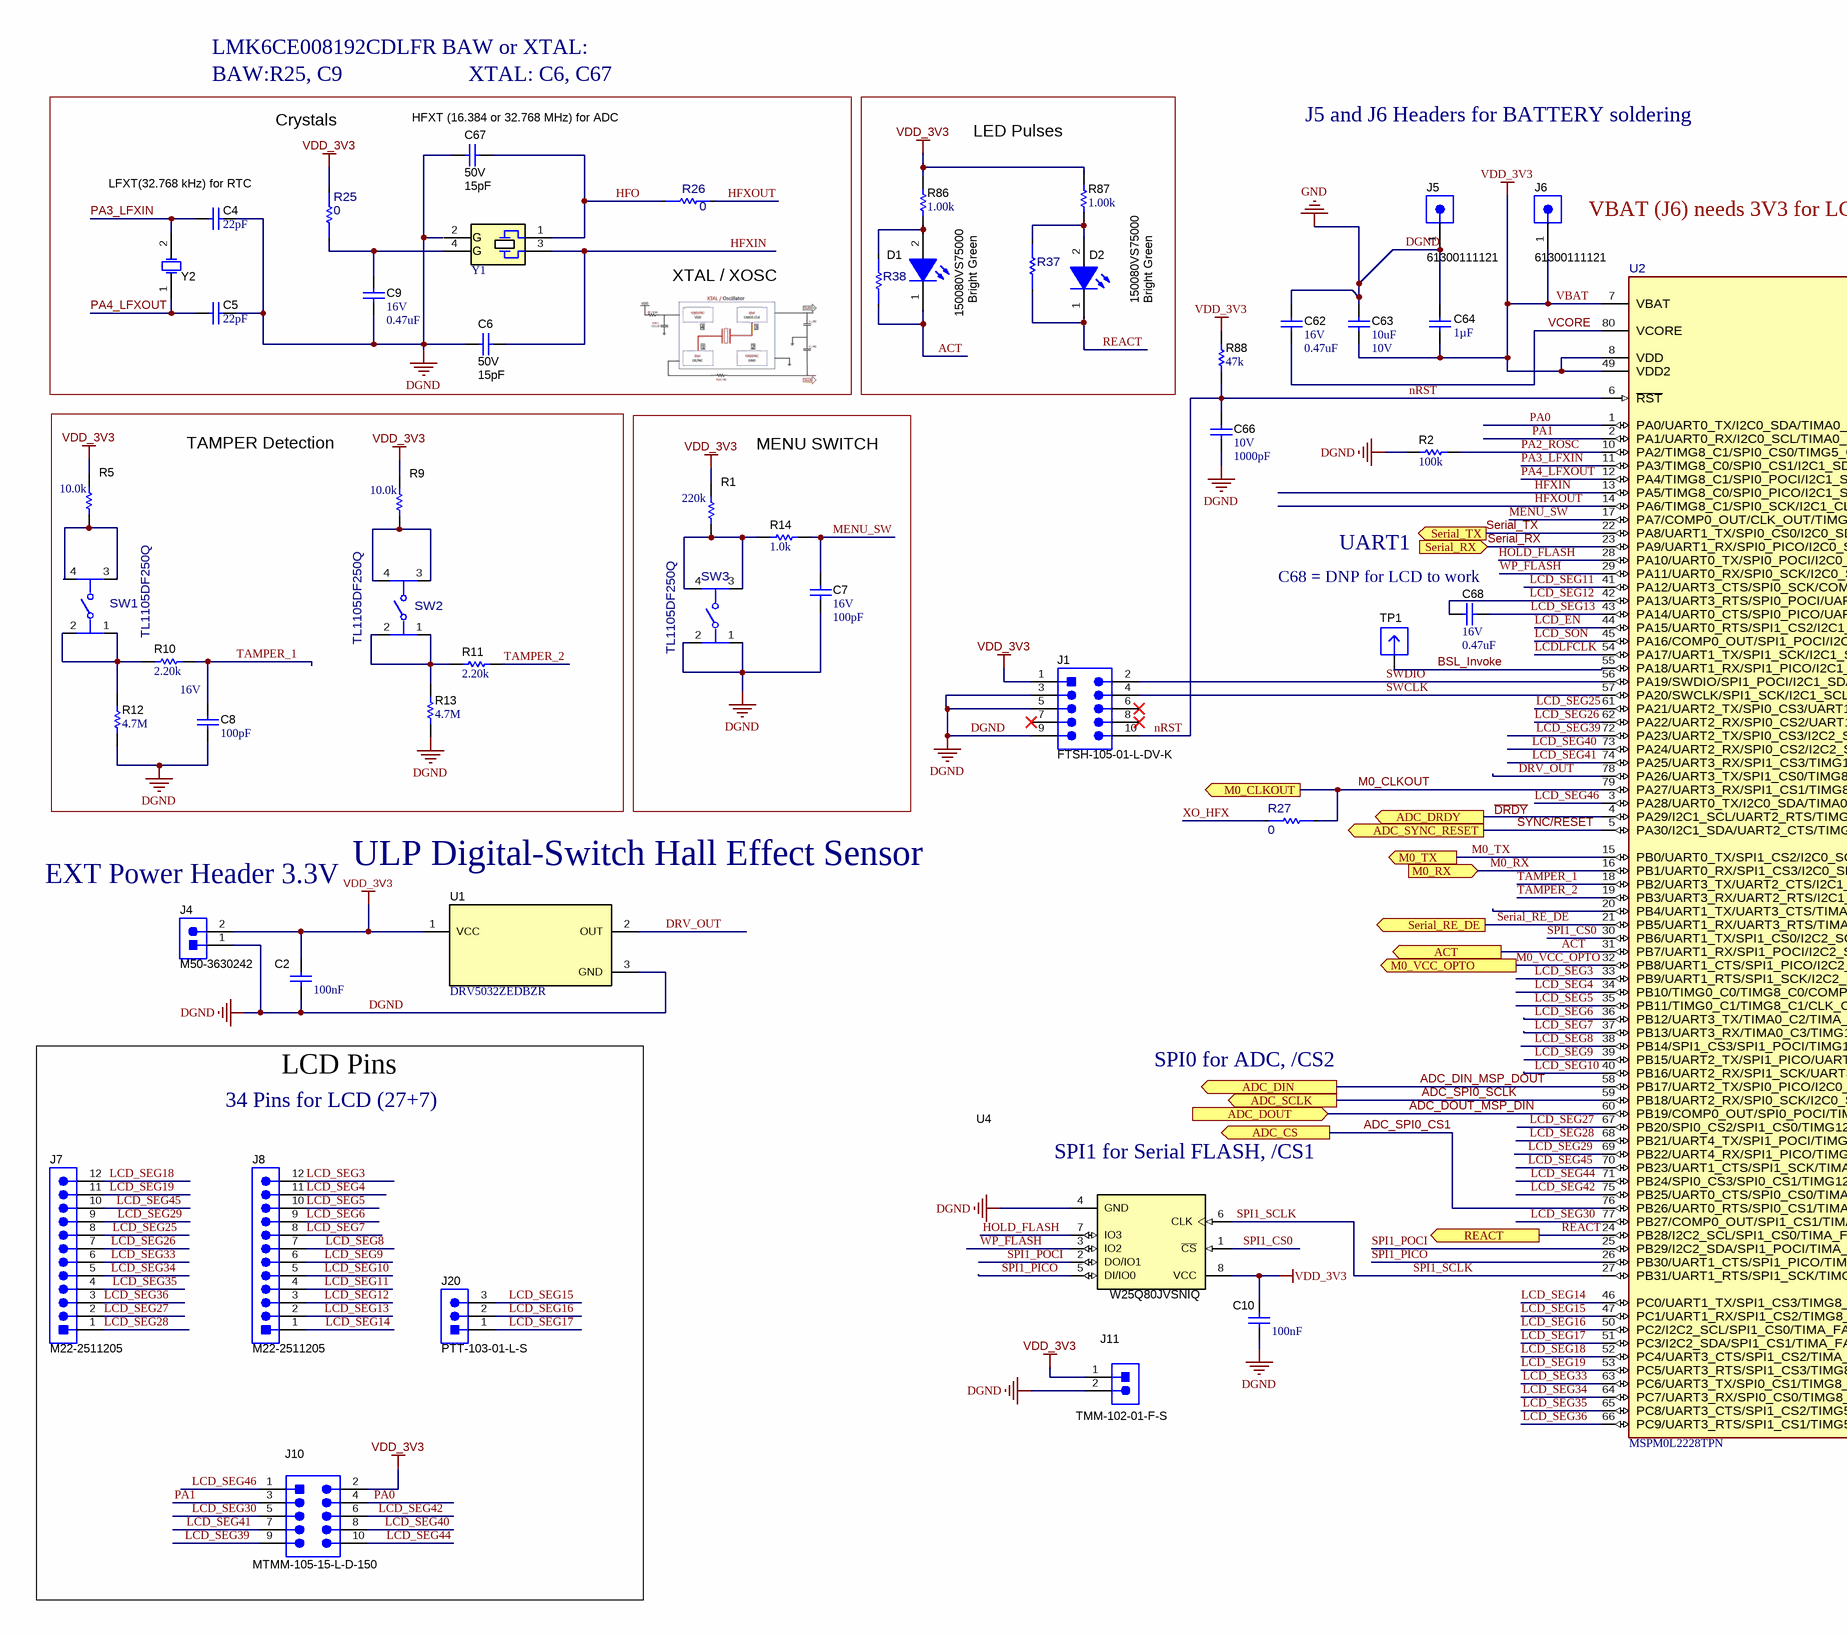
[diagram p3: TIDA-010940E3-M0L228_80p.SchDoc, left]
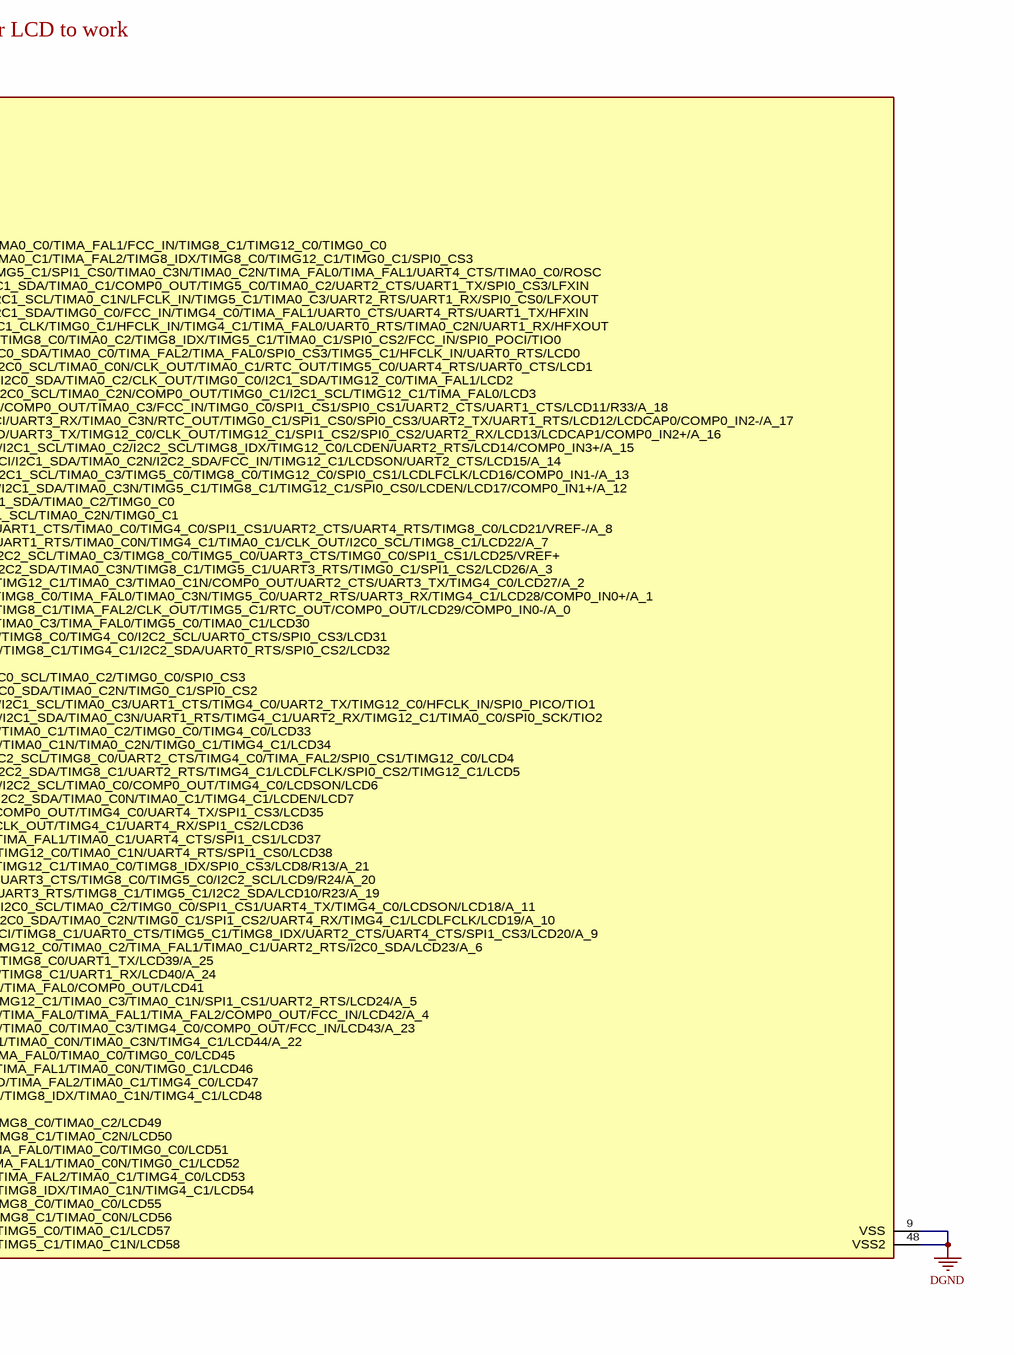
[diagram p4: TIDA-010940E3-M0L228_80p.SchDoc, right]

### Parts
C2  Cap_F: 100nF  [0402]  (hidden comment: GRM155R71E104KE14D)
C4  ValueDisplayed: 22pF  [0402]  (hidden comment: GRM1555C1H220JA01D)
C5  ValueDisplayed: 22pF  [0402]  (hidden comment: GRM1555C1H220JA01D)
C6  VDC_V: 50V  ValueDisplayed: 15pF  [0402]  (hidden comment: GRM1555C1H150JA01D)
C7  VDC_V: 16V  ValueDisplayed: 100pF  [0402]  (hidden comment: 0402YC101KAT2A)
C8  ValueDisplayed: 100pF  VDC_V: 16V  [0402]  (hidden comment: 0402YC101KAT2A)
C9  VDC_V: 16V  ValueDisplayed: 0.47uF  [0402]  (hidden comment: GRM155R61C474KE01)
C10  Cap_F: 100nF  [0402]  (hidden comment: GRM155R71E104KE14D)
C62  VDC_V: 16V  ValueDisplayed: 0.47uF  [0402]  (hidden comment: GRM155R61C474KE01)
C63  ValueDisplayed: 10uF  VDC_V: 10V  [0402]  (hidden comment: GRM155R61A106ME11D)
C64  ValueDisplayed: 1µF  [0402]  (hidden comment: GRM155R61E105KE11D)
C66  VDC_V: 10V  ValueDisplayed: 1000pF  [0402]  (hidden comment: GRM155R61A102KA01D)
C67  VDC_V: 50V  ValueDisplayed: 15pF  [0402]  (hidden comment: GRM1555C1H150JA01D)
C68  VDC_V: 16V  ValueDisplayed: 0.47uF  [0402]  (hidden comment: GRM155R61C474KE01)
D1  150080VS75000  value Bright Green  [WL-SMCW_Green_0805]
D2  150080VS75000  value Bright Green  [WL-SMCW_Green_0805]
J1  FTSH-105-01-L-DV-K  [Samtec_FTSH-105-01-x-DV-K]
J4  M50-3630242  [Harwin_M50-3630242]
J5  61300111121  [WURTH_61300111121]
J6  61300111121  [WURTH_61300111121]
J7  M22-2511205  [Harwin_M22-2511205]
J8  M22-2511205  [Harwin_M22-2511205]
J10  MTMM-105-15-L-D-150  [Samtec_MTMM-105-15-x-D-150]
J11  TMM-102-01-F-S  [Samtec_TMM-102-01-F-S]
J20  PTT-103-01-L-S  [Samtec_PTT-103-01-x-S]
R1  ValueDisplayed: 220k  [0402]  (hidden comment: RC0402FR-07220KL)
R2  ValueDisplayed: 100k  [0402]  (hidden comment: RG1005P-104-B-T5)
R5  ValueDisplayed: 10.0k  [0402]  (hidden comment: ERJ-2RKF1002X)
R9  ValueDisplayed: 10.0k  [0402]  (hidden comment: ERJ-2RKF1002X)
R10  ValueDisplayed: 2.20k  [0402]  (hidden comment: RC0402FR-072K2L)
R11  ValueDisplayed: 2.20k  [0402]  (hidden comment: RC0402FR-072K2L)
R12  ValueDisplayed: 4.7M  [0402]  (hidden comment: CRCW04024M70JNED)
R13  ValueDisplayed: 4.7M  [0402]  (hidden comment: CRCW04024M70JNED)
R14  ValueDisplayed: 1.0k  [0402]  (hidden comment: CRCW04021K00JNED)
R25  0  [FP-5113_0402-MFG]
R26  0  [FP-5113_0402-MFG]
R27  0  [FP-5113_0402-MFG]
R37  RC0805FR-070RL  [FP-RC0805FR-070RL_0805-MFG]  (value not drawn)
R38  RC0805FR-070RL  [FP-RC0805FR-070RL_0805-MFG]  (value not drawn)
R86  ValueDisplayed: 1.00k  [0402]  (hidden comment: RC0402FR-071KL)
R87  ValueDisplayed: 1.00k  [0402]  (hidden comment: RC0402FR-071KL)
R88  ValueDisplayed: 47k  [0402]  (hidden comment: CRCW040247K0JNED)
SW1  TL1105DF250Q  [FP-TL1105DF250Q_PTH_SW_6MM0_6MM0-MFG]
SW2  TL1105DF250Q  [FP-TL1105DF250Q_PTH_SW_6MM0_6MM0-MFG]
SW3  TL1105DF250Q  [FP-TL1105DF250Q_PTH_SW_6MM0_6MM0-MFG]
TP1  3154-0-00-15-00-00-03-0  [Mill-Max_3154-0-00-15-00-00-03-0]  (value not drawn)
U1  DRV5032ZEDBZR  [DBZ0003A_N]
U2  MSPM0L2228TPN  [PN0080A-MFG]
U4  W25Q80JVSNIQ  [SOIC-8]
Y1  FA-238 16.3840MB-K  [Epson_FA-238]  (value not drawn)
Y2  X1A0001410014  [Epson_FC-135]  (value not drawn)

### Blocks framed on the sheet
LED Pulses: D1 D2 R37 R38 R86 R87
TAMPER Detection: C8 R5 R9-R13 SW1 SW2
MENU SWITCH: C7 R1 R14 SW3

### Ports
ACT (out), ADC_CS (out), ADC_DIN (out), ADC_DOUT (in), ADC_DRDY (out), ADC_SCLK (out), ADC_SYNC_RESET (out), M0_CLKOUT (out), M0_RX (in), M0_TX (out), M0_VCC_OPTO (out), REACT (out), Serial_RE_DE (out), Serial_RX (in), Serial_TX (out)

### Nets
DGND: C2.2 C4.1 C5.1 C6.2 C7.2 C8.2 C9.2 C10.2 C62.1 C63.1 C64.2 C66.2 C67.2 J1.3 J1.5 J1.9 J4.1 J5.1 J11.2 R2.1 R12.1 R13.1 SW3.1 SW3.2 U1.3(GND) U2.9(VSS) U2.48(VSS2) U4.4(GND)  [also labelled GND]
VBAT: C2.1 C10.1 C63.2 C64.1 J1.1 J4.2 J6.1 J10.2 J11.1 R1.2 R5.2 R9.2 R25.2 R86.2 R87.2 R88.2 U1.1(VCC) U2.7(VBAT) U2.8(VDD) U2.49(VDD2) U4.8(VCC)  [also labelled VDD_3V3]  [project net DVDD]
ACT: D1.1(K) R38.1 U2.31(PB7/UART1_RX/SPI1_POCI/I2C2_SDA/TIMG8_C1/UART2_RTS/TIMG4_C1/LCDLFCLK/SPI0_CS2/TIMG12_C1/LCD5) ; port ACT
ADC_DIN_MSP_DOUT: U2.58(PB17/UART2_TX/SPI0_PICO/I2C0_SCL/TIMA0_C2/TIMG0_C0/SPI1_CS1/UART4_TX/TIMG4_C0/LCDSON/LCD18/A_11) ; port ADC_DIN  [project net ADC_DIN]
ADC_DOUT_MSP_DIN: U2.60(PB19/COMP0_OUT/SPI0_POCI/TIMG8_C1/UART0_CTS/TIMG5_C1/TIMG8_IDX/UART2_CTS/UART4_CTS/SPI1_CS3/LCD20/A_9) ; port ADC_DOUT  [project net ADC_DOUT]
ADC_SPI0_CS1: U2.76(PB26/UART0_RTS/SPI0_CS1/TIMA0_C0/TIMA0_C3/TIMG4_C0/COMP0_OUT/FCC_IN/LCD43/A_23) ; port ADC_CS
ADC_SPI0_SCLK: U2.59(PB18/UART2_RX/SPI0_SCK/I2C0_SDA/TIMA0_C2N/TIMG0_C1/SPI1_CS2/UART4_RX/TIMG4_C1/LCDLFCLK/LCD19/A_10) ; port ADC_SCLK
BSL_Invoke: TP1.1 U2.55(PA18/UART1_RX/SPI1_PICO/I2C1_SDA/TIMA0_C3N/TIMG5_C1/TIMG8_C1/TIMG12_C1/SPI0_CS0/LCDEN/LCD17/COMP0_IN1+/A_12)
~{DRDY}: U2.4(PA29/I2C1_SCL/UART2_RTS/TIMG8_C0/TIMG4_C0/I2C2_SCL/UART0_CTS/SPI0_CS3/LCD31) ; port ADC_DRDY
DRV_OUT: U1.2(OUT) U2.78(PA26/UART3_TX/SPI1_CS0/TIMG8_C0/TIMA_FAL0/TIMA0_C3N/TIMG5_C0/UART2_RTS/UART3_RX/TIMG4_C1/LCD28/COMP0_IN0+/A_1)
HFO: C67.1 R26.1 Y1.1
HFXIN: C6.1 U2.13(PA5/TIMG8_C0/SPI0_PICO/I2C1_SDA/TIMG0_C0/FCC_IN/TIMG4_C0/TIMA_FAL1/UART0_CTS/UART4_RTS/UART1_TX/HFXIN) Y1.3
HFXOUT: R26.2 U2.14(PA6/TIMG8_C1/SPI0_SCK/I2C1_CLK/TIMG0_C1/HFCLK_IN/TIMG4_C1/TIMA_FAL0/UART0_RTS/TIMA0_C2N/UART1_RX/HFXOUT)
HOLD_FLASH: U2.28(PA10/UART0_TX/SPI0_POCI/I2C0_SDA/TIMA0_C2/CLK_OUT/TIMG0_C0/I2C1_SDA/TIMG12_C0/TIMA_FAL1/LCD2) U4.7(IO3)
LCD_EN: U2.44(PA15/UART0_RTS/SPI1_CS2/I2C1_SCL/TIMA0_C2/I2C2_SCL/TIMG8_IDX/TIMG12_C0/LCDEN/UART2_RTS/LCD14/COMP0_IN3+/A_15)
LCD_SEG3: J8.12 U2.33(PB9/UART1_RTS/SPI1_SCK/I2C2_SDA/TIMA0_C0N/TIMA0_C1/TIMG4_C1/LCDEN/LCD7)
LCD_SEG4: J8.11 U2.34(PB10/TIMG0_C0/TIMG8_C0/COMP0_OUT/TIMG4_C0/UART4_TX/SPI1_CS3/LCD35)
LCD_SEG5: J8.10 U2.35(PB11/TIMG0_C1/TIMG8_C1/CLK_OUT/TIMG4_C1/UART4_RX/SPI1_CS2/LCD36)
LCD_SEG6: J8.9 U2.36(PB12/UART3_TX/TIMA0_C2/TIMA_FAL1/TIMA0_C1/UART4_CTS/SPI1_CS1/LCD37)
LCD_SEG7: J8.8 U2.37(PB13/UART3_RX/TIMA0_C3/TIMG12_C0/TIMA0_C1N/UART4_RTS/SPI1_CS0/LCD38)
LCD_SEG8: J8.7 U2.38(PB14/SPI1_CS3/SPI1_POCI/TIMG12_C1/TIMA0_C0/TIMG8_IDX/SPI0_CS3/LCD8/R13/A_21)
LCD_SEG9: J8.6 U2.39(PB15/UART2_TX/SPI1_PICO/UART3_CTS/TIMG8_C0/TIMG5_C0/I2C2_SCL/LCD9/R24/A_20)
LCD_SEG10: J8.5 U2.40(PB16/UART2_RX/SPI1_SCK/UART3_RTS/TIMG8_C1/TIMG5_C1/I2C2_SDA/LCD10/R23/A_19)
LCD_SEG11: J8.4 U2.41(PA12/UART3_CTS/SPI0_SCK/COMP0_OUT/TIMA0_C3/FCC_IN/TIMG0_C0/SPI1_CS1/SPI0_CS1/UART2_CTS/UART1_CTS/LCD11/R33/A_18)
LCD_SEG12: C68.1 J8.3 U2.42(PA13/UART3_RTS/SPI0_POCI/UART3_RX/TIMA0_C3N/RTC_OUT/TIMG0_C1/SPI1_CS0/SPI0_CS3/UART2_TX/UART1_RTS/LCD12/LCDCAP0/COMP0_IN2-/A_17)
LCD_SEG13: C68.2 J8.2 U2.43(PA14/UART0_CTS/SPI0_PICO/UART3_TX/TIMG12_C0/CLK_OUT/TIMG12_C1/SPI1_CS2/SPI0_CS2/UART2_RX/LCD13/LCDCAP1/COMP0_IN2+/A_16)
LCD_SEG14: J8.1 U2.46(PC0/UART1_TX/SPI1_CS3/TIMG8_C0/TIMA0_C2/LCD49)
LCD_SEG15: J20.3 U2.47(PC1/UART1_RX/SPI1_CS2/TIMG8_C1/TIMA0_C2N/LCD50)
LCD_SEG16: J20.2 U2.50(PC2/I2C2_SCL/SPI1_CS0/TIMA_FAL0/TIMA0_C0/TIMG0_C0/LCD51)
LCD_SEG17: J20.1 U2.51(PC3/I2C2_SDA/SPI1_CS1/TIMA_FAL1/TIMA0_C0N/TIMG0_C1/LCD52)
LCD_SEG18: J7.12 U2.52(PC4/UART3_CTS/SPI1_CS2/TIMA_FAL2/TIMA0_C1/TIMG4_C0/LCD53)
LCD_SEG19: J7.11 U2.53(PC5/UART3_RTS/SPI1_CS3/TIMG8_IDX/TIMA0_C1N/TIMG4_C1/LCD54)
LCD_SEG25: J7.8 U2.61(PA21/UART2_TX/SPI0_CS3/UART1_CTS/TIMA0_C0/TIMG4_C0/SPI1_CS1/UART2_CTS/UART4_RTS/TIMG8_C0/LCD21/VREF-/A_8)
LCD_SEG26: J7.7 U2.62(PA22/UART2_RX/SPI0_CS2/UART1_RTS/TIMA0_C0N/TIMG4_C1/TIMA0_C1/CLK_OUT/I2C0_SCL/TIMG8_C1/LCD22/A_7)
LCD_SEG27: J7.2 U2.67(PB20/SPI0_CS2/SPI1_CS0/TIMG12_C0/TIMA0_C2/TIMA_FAL1/TIMA0_C1/UART2_RTS/I2C0_SDA/LCD23/A_6)
LCD_SEG28: J7.1 U2.68(PB21/UART4_TX/SPI1_POCI/TIMG8_C0/UART1_TX/LCD39/A_25)
LCD_SEG29: J7.9 U2.69(PB22/UART4_RX/SPI1_PICO/TIMG8_C1/UART1_RX/LCD40/A_24)
LCD_SEG30: J10.5 U2.77(PB27/COMP0_OUT/SPI1_CS1/TIMA0_C0N/TIMA0_C3N/TIMG4_C1/LCD44/A_22)
LCD_SEG33: J7.6 U2.63(PC6/UART3_TX/SPI0_CS1/TIMG8_C0/TIMA0_C0/LCD55)
LCD_SEG34: J7.5 U2.64(PC7/UART3_RX/SPI0_CS0/TIMG8_C1/TIMA0_C0N/LCD56)
LCD_SEG35: J7.4 U2.65(PC8/UART3_CTS/SPI1_CS2/TIMG5_C0/TIMA0_C1/LCD57)
LCD_SEG36: J7.3 U2.66(PC9/UART3_RTS/SPI1_CS1/TIMG5_C1/TIMA0_C1N/LCD58)
LCD_SEG39: J10.9 U2.72(PA23/UART2_TX/SPI0_CS3/I2C2_SCL/TIMA0_C3/TIMG8_C0/TIMG5_C0/UART3_CTS/TIMG0_C0/SPI1_CS1/LCD25/VREF+)
LCD_SEG40: J10.8 U2.73(PA24/UART2_RX/SPI0_CS2/I2C2_SDA/TIMA0_C3N/TIMG8_C1/TIMG5_C1/UART3_RTS/TIMG0_C1/SPI1_CS2/LCD26/A_3)
LCD_SEG41: J10.7 U2.74(PA25/UART3_RX/SPI1_CS3/TIMG12_C1/TIMA0_C3/TIMA0_C1N/COMP0_OUT/UART2_CTS/UART3_TX/TIMG4_C0/LCD27/A_2)
LCD_SEG42: J10.6 U2.75(PB25/UART0_CTS/SPI0_CS0/TIMA_FAL0/TIMA_FAL1/TIMA_FAL2/COMP0_OUT/FCC_IN/LCD42/A_4)
LCD_SEG44: J10.10 U2.71(PB24/SPI0_CS3/SPI0_CS1/TIMG12_C1/TIMA0_C3/TIMA0_C1N/SPI1_CS1/UART2_RTS/LCD24/A_5)
LCD_SEG45: J7.10 U2.70(PB23/UART1_CTS/SPI1_SCK/TIMA_FAL0/COMP0_OUT/LCD41)
LCD_SEG46: J10.1 U2.3(PA28/UART0_TX/I2C0_SDA/TIMA0_C3/TIMA_FAL0/TIMG5_C0/TIMA0_C1/LCD30)
LCD_SON: U2.45(PA16/COMP0_OUT/SPI1_POCI/I2C1_SDA/TIMA0_C2N/I2C2_SDA/FCC_IN/TIMG12_C1/LCDSON/UART2_CTS/LCD15/A_14)
LCDLFCLK: U2.54(PA17/UART1_TX/SPI1_SCK/I2C1_SCL/TIMA0_C3/TIMG5_C0/TIMG8_C0/TIMG12_C0/SPI0_CS1/LCDLFCLK/LCD16/COMP0_IN1-/A_13)
M0_CLKOUT: R27.2 U2.79(PA27/UART3_RX/SPI1_CS1/TIMG8_C1/TIMA_FAL2/CLK_OUT/TIMG5_C1/RTC_OUT/COMP0_OUT/LCD29/COMP0_IN0-/A_0) ; port M0_CLKOUT  [project net CLKIN]
M0_RX: U2.16(PB1/UART0_RX/SPI1_CS3/I2C0_SDA/TIMA0_C2N/TIMG0_C1/SPI0_CS2) ; port M0_RX
M0_TX: U2.15(PB0/UART0_TX/SPI1_CS2/I2C0_SCL/TIMA0_C2/TIMG0_C0/SPI0_CS3) ; port M0_TX
M0_VCC_OPTO: U2.32(PB8/UART1_CTS/SPI1_PICO/I2C2_SCL/TIMA0_C0/COMP0_OUT/TIMG4_C0/LCDSON/LCD6) ; port M0_VCC_OPTO
MENU_SW: C7.1 R14.2 U2.17(PA7/COMP0_OUT/CLK_OUT/TIMG8_C0/TIMA0_C2/TIMG8_IDX/TIMG5_C1/TIMA0_C1/SPI0_CS2/FCC_IN/SPI0_POCI/TIO0)
nRST: C66.1 J1.10 R88.1 U2.6(~{RST})
PA0: J10.4 U2.1(PA0/UART0_TX/I2C0_SDA/TIMA0_C0/TIMA_FAL1/FCC_IN/TIMG8_C1/TIMG12_C0/TIMG0_C0)
PA1: J10.3 U2.2(PA1/UART0_RX/I2C0_SCL/TIMA0_C1/TIMA_FAL2/TIMG8_IDX/TIMG8_C0/TIMG12_C1/TIMG0_C1/SPI0_CS3)
PA2_ROSC: R2.2 U2.10(PA2/TIMG8_C1/SPI0_CS0/TIMG5_C1/SPI1_CS0/TIMA0_C3N/TIMA0_C2N/TIMA_FAL0/TIMA_FAL1/UART4_CTS/TIMA0_C0/ROSC)
PA3_LFXIN: C4.2 U2.11(PA3/TIMG8_C0/SPI0_CS1/I2C1_SDA/TIMA0_C1/COMP0_OUT/TIMG5_C0/TIMA0_C2/UART2_CTS/UART1_TX/SPI0_CS3/LFXIN) Y2.2(OSC2)
PA4_LFXOUT: C5.2 U2.12(PA4/TIMG8_C1/SPI0_POCI/I2C1_SCL/TIMA0_C1N/LFCLK_IN/TIMG5_C1/TIMA0_C3/UART2_RTS/UART1_RX/SPI0_CS0/LFXOUT) Y2.1(OSC1)
REACT: D2.1(K) R37.1 U2.24(PB28/I2C2_SCL/SPI1_CS0/TIMA_FAL0/TIMA0_C0/TIMG0_C0/LCD45) ; port REACT
~{SYNC}/~{RESET}: U2.5(PA30/I2C1_SDA/UART2_CTS/TIMG8_C1/TIMG4_C1/I2C2_SDA/UART0_RTS/SPI0_CS2/LCD32) ; port ADC_SYNC_RESET
Serial_RE_DE: U2.21(PB5/UART1_RX/UART3_RTS/TIMA0_C1N/TIMA0_C2N/TIMG0_C1/TIMG4_C1/LCD34) ; port Serial_RE_DE
Serial_RX: U2.23(PA9/UART1_RX/SPI0_PICO/I2C0_SCL/TIMA0_C0N/CLK_OUT/TIMA0_C1/RTC_OUT/TIMG5_C0/UART4_RTS/UART0_CTS/LCD1) ; port Serial_RX
Serial_TX: U2.22(PA8/UART1_TX/SPI0_CS0/I2C0_SDA/TIMA0_C0/TIMA_FAL2/TIMA_FAL0/SPI0_CS3/TIMG5_C1/HFCLK_IN/UART0_RTS/LCD0) ; port Serial_TX
SPI1_CS0: U2.30(PB6/UART1_TX/SPI1_CS0/I2C2_SCL/TIMG8_C0/UART2_CTS/TIMG4_C0/TIMA_FAL2/SPI0_CS1/TIMG12_C0/LCD4) U4.1(~{CS})
SPI1_PICO: U2.26(PB30/UART1_CTS/SPI1_PICO/TIMA_FAL2/TIMA0_C1/TIMG4_C0/LCD47) U4.5(DI/IO0)
SPI1_POCI: U2.25(PB29/I2C2_SDA/SPI1_POCI/TIMA_FAL1/TIMA0_C0N/TIMG0_C1/LCD46) U4.2(DO/IO1)
SPI1_SCLK: U2.27(PB31/UART1_RTS/SPI1_SCK/TIMG8_IDX/TIMA0_C1N/TIMG4_C1/LCD48) U4.6(CLK)
SWCLK: J1.4 U2.57(PA20/SWCLK/SPI1_SCK/I2C1_SCL/TIMA0_C2N/TIMG0_C1)
SWDIO: J1.2 U2.56(PA19/SWDIO/SPI1_POCI/I2C1_SDA/TIMA0_C2/TIMG0_C0)
TAMPER_1: C8.1 R10.2 U2.18(PB2/UART3_TX/UART2_CTS/I2C1_SCL/TIMA0_C3/UART1_CTS/TIMG4_C0/UART2_TX/TIMG12_C0/HFCLK_IN/SPI0_PICO/TIO1)
TAMPER_2: R11.2 U2.19(PB3/UART3_RX/UART2_RTS/I2C1_SDA/TIMA0_C3N/UART1_RTS/TIMG4_C1/UART2_RX/TIMG12_C1/TIMA0_C0/SPI0_SCK/TIO2)
VCORE: C62.2 U2.80(VCORE)
WP_FLASH: U2.29(PA11/UART0_RX/SPI0_SCK/I2C0_SCL/TIMA0_C2N/COMP0_OUT/TIMG0_C1/I2C1_SCL/TIMG12_C1/TIMA_FAL0/LCD3) U4.3(IO2)
XO_HFX: R27.1
NetC9_1: C9.1 R25.1 Y1.4(GND)
NetD1_2: D1.2(A) R38.2 R86.1
NetD2_2: D2.2(A) R37.2 R87.1
NetR1_1: R1.1 R14.1 SW3.3 SW3.4
NetR5_1: R5.1 SW1.3 SW1.4
NetR9_1: R9.1 SW2.3 SW2.4
NetR10_1: R10.1 R12.2 SW1.1 SW1.2
NetR11_1: R11.1 R13.2 SW2.1 SW2.2

Not connected (* = marked no-connect by the designer): J1 6* 7* 8*; U2 20(PB4/UART1_TX/UART3_CTS/TIMA0_C1/TIMA0_C2/TIMG0_C0/TIMG4_C0/LCD33); Y1 2(GND)

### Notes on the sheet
- LMK6CE008192CDLFR BAW or XTAL:
- BAW:R25, C9
- Crystals
- (near C67) HFXT (16.384 or 32.768 MHz) for ADC
- XTAL: C6, C67
- J5 and J6 Headers for BATTERY soldering
- (near C4) LFXT(32.768 kHz) for RTC
- (near J6) VBAT (J6) needs 3V3 for LCD to work
- XTAL / XOSC
- (near C68) C68 = DNP for LCD to work
- UART1
- ULP Digital-Switch Hall Effect Sensor
- (near J4) EXT Power Header 3.3V
- SPI0 for ADC, /CS2
- 34 Pins for LCD (27+7)
- (near U4) SPI1 for Serial FLASH, /CS1
- LCD Pins
- Labels drawn without touching a wire or pin: ~{DRDY}

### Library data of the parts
C2 C10 = CMP-0006659-2: CAP, CERM, 0.1 uF, 25 V, +/- 10%, X7R, 0402; Manufacturer: MuRata; TaMin_C: -55°C; Polarized: N; SizeAreaWB_mm2: 3; Value1: Unknown; U/M: EA; Value: 0.1uF; TaMax_C: 125°C; SizeZ_mm: 0.6; SizeX_mm: 1; SizeY_mm: 0.5; Value2: 25V; AEC Category: Q200
C4 C5 = CMP-0006439-2: CAP, CERM, 22 pF, 50 V, +/- 5%, C0G/NP0, 0402; Manufacturer: MuRata; TaMin_C: -55°C; Polarized: N; SizeAreaWB_mm2: 3; Value1: Unknown; U/M: EA; Value: 22pF; TaMax_C: 125°C; SizeZ_mm: 0.6; SizeX_mm: 1; SizeY_mm: 0.5; Value2: 50V; AEC Category: Q200
C6 C67 = CMP-0006420-2: CAP, CERM, 15 pF, 50 V, +/- 5%, C0G/NP0, 0402; Manufacturer: MuRata; TaMin_C: -55°C; Polarized: N; SizeAreaWB_mm2: 3; Value1: Unknown; U/M: EA; Value: 15pF; TaMax_C: 125°C; SizeZ_mm: 0.6; SizeX_mm: 1; SizeY_mm: 0.5; AEC Category: Q200
C7 C8 = CMP-0006200-2: CAP, CERM, 100 pF, 16 V, +/- 10%, X7R, 0402; Manufacturer: AVX; TaMin_C: -55°C; Polarized: N; SizeAreaWB_mm2: 3; Value1: Unknown; U/M: EA; Value: 100pF; TaMax_C: 125°C; SizeZ_mm: 0.6; SizeX_mm: 1; SizeY_mm: 0.5; AEC Category: Q200
C9 C62 C68 = CMP-0006600-2: CAP, CERM, 0.47 uF, 16 V, +/- 10%, X5R, 0402; Manufacturer: MuRata; TaMin_C: -55°C; Polarized: N; SizeAreaWB_mm2: 3; Value1: Unknown; U/M: EA; Value: 0.47uF; TaMax_C: 85°C; SizeZ_mm: 0.6; SizeX_mm: 1; SizeY_mm: 0.5; Cap_F: 470nF; AEC Category: Q200
C63 = CMP-0006564-3: CAP, CERM, 10 uF, 10 V, +/- 20%, X5R, 0402; Manufacturer: MuRata; SizeArea_mm2: 0.5; TaMax_C: 85°C; TaMin_C: -55°C; Polarized: N; SizeAreaWB_mm2: 3; SizeZ_mm: 0.6; SizeX_mm: 1; Value1: Unknown; AEC Category: Q200; U/M: EA; Cap_F: 10µF; Value: 10uF
C64 = CMP-0086061-1: CAP, CERM, 1 µF, 25 V,+/- 10%, X5R, 0402; Manufacturer: MuRata; TaMin_C: -55°C; Polarized: N; SizeAreaWB_mm2: 3; U/M: EA; Value: 1uF; TaMax_C: 85°C; SizeZ_mm: 0.6; SizeX_mm: 1; SizeY_mm: 0.5; Value2: 25V; AEC Category: Q200
C66 = CMP-0006560-2: CAP, CERM, 1000 pF, 10 V, +/- 10%, X5R, 0402; Manufacturer: MuRata; TaMin_C: -55°C; Polarized: N; SizeAreaWB_mm2: 3; Value1: Unknown; U/M: EA; Value: 1000pF; TaMax_C: 85°C; SizeZ_mm: 0.6; SizeX_mm: 1; SizeY_mm: 0.5; Cap_F: 1nF; AEC Category: Q200
D1 D2 = CMP-0002960-2: LED, Bright Green, SMD; Manufacturer: Wurth Elektronik; Power_TotalModule: 72mW; Vr_V: 5V; Angle: 140; Vf_V: 2V; Io_A: 20mA; Tjmax_C: 85°C; Value1: 0.072W; U/M: EA; Type: AlInGaP
J1 = CMP-0075634-2: Header(Shrouded), 1.27mm, 5x2, Gold, SMT; Manufacturer: Samtec; Pitch_mm: 1.27; Gender: Male; Shrouded: Y; Row_Count: 2; Current_A: 3.3A
J4 = CMP-0079909-1: Header, 1.27mm, 2x1, Gold with Tin tail, SMT; Manufacturer: Harwin; Current_A: 1A; Shrouded: N; Gender: Male; Voltage_V: 500V; Row_Count: 1; Pitch_mm: 1.27; Cert_UL: Y
J5 J6 = CMP-0054792-1: Header, 2.54 mm, 1x1, Gold, TH; Manufacturer: Wurth Elektronik; CNHeader: TRUE; CT: FALSE
J7 J8 = CMP-0075238-1: Header, 2mm, 12x1, Gold, TH; Manufacturer: Harwin; CNHeader: True; Current_A: 1A; Shrouded: N; Gender: Male; Voltage_V: 500V; Row_Count: 1; Pitch_mm: 2; CT: False; Cert_UL: Y
J10 = CMP-0055583-2: Header, 2mm, 5x2, Gold, TH; Manufacturer: Samtec; Cert_UL: Y; Gender: Male; Pitch_mm: 2; Shrouded: N
J11 = CMP-0075560-1: Header, 2mm, 2x1, Gold, TH; Manufacturer: Samtec; Shrouded: N; Gender: Male; Row_Count: 1; Pitch_mm: 2; CT: False; CNHeader: True
J20 = CMP-0055571-1: Header, 2mm, 3x1, Gold, TH; Manufacturer: Samtec; CNHeader: TRUE; Current_A: 2.9A; Shrouded: N; Gender: Male; Pitch_mm: 2; CT: FALSE; Cert_UL: Y
R1 = CMP-0026728-1: RES, 220 k, 1%, 0.0625 W, 0402; Manufacturer: Yageo America; Power_W: 62.5mW; TempCo: 100 ppm/C; Value: 220k; SizeZ_mm: 0.6; AEC Qualified: N; VDC_V: 50V; U/M: EA; SizeX_mm: 1; SizeY_mm: 0.5; AEC Category: Q200
R2 = CMP-0026815-1: RES, 100 k, 0.1%, 0.063 W, 0402; Manufacturer: Susumu Co Ltd; Power_W: 63mW; TempCo: 25 ppm/C; U/M: EA; Value: 100k; EIA_Code: E192; SizeX_mm: 1; SizeY_mm: 0.5; SizeZ_mm: 0.6; Value2: 0.063W; AEC Category: Q200
R5 R9 = CMP-0026658-1: RES, 10.0 k, 1%, 0.1 W, 0402; Manufacturer: Panasonic; Power_W: 100mW; TempCo: 100 ppm/C; Value: 10.0k; Res_ohm: 10k; SizeZ_mm: 0.6; VDC_V: 50V; Value_Code: 10k0; U/M: EA; EIA_Code: E96; SizeX_mm: 1; SizeY_mm: 0.5; Value2: 0.1W; AEC Category: Q200
R10 R11 = CMP-0026729-1: RES, 2.20 k, 1%, 0.063 W, 0402; Manufacturer: Yageo America; Power_W: 63mW; TempCo: 100 ppm/C; Value_Code: 2k20; U/M: EA; Value: 2.20k; Res_ohm: 2.2k; SizeX_mm: 1; SizeY_mm: 0.5; SizeZ_mm: 0.6; Value2: 0.063W; AEC Qualified: N; AEC Category: Q200
R12 R13 = CMP-0026940-2: RES, 4.7 M, 5%, 0.063 W, AEC-Q200 Grade 0, 0402; Manufacturer: Vishay-Dale; Power_W: 63mW; TempCo: 200 ppm/C; Value_Code: 4M70; Value: 4.7Meg; EIA_Code: E24; SizeX_mm: 1; SizeY_mm: 0.5; SizeZ_mm: 0.6; Value2: 0.063W; AEC Qualified: Y; VDC_V: 50V; AEC Category: Q200; AEC Grade: 0
R14 = CMP-0026852-3: RES, 1.0 k, 5%, 0.063 W, AEC-Q200 Grade 0, 0402; Manufacturer: Vishay-Dale; Power_W: 63mW; TempCo: 200 ppm/C; Value_Code: 1k00; Value: 1.0k; Res_ohm: 1k; SizeX_mm: 1; SizeY_mm: 0.5; SizeZ_mm: 0.6; Value2: 0.063W; AEC Qualified: Y; AEC Grade: 0; AEC Category: Q200; EIA_Code: E24; VDC_V: 50V
R25-R27 = CMP-0120020-1: 0 Ohms Jumper Chip Resistor 0402 (1005 Metric) Metal Element; Manufacturer: Keystone Electronics; PartNumber: 5113; AEC Qualified: No; SizeZ_mm: 0.63mm
R37 R38 = CMP-0092692-1: RES SMD 0 OHM JUMPER 1/8W 0805; Manufacturer: Yageo; Res_ohm: 0; AEC Qualified: No; SizeZ_mm: 0.6mm; Value: 0; VDC_V: 150V; Power_W: 125mW; Tolerance_%: 1%
R86 R87 = CMP-0026725-1: as R18 on sheet TIDA-010940E3-Interfaces
R88 = CMP-0026935-3: RES, 47 k, 5%, 0.063 W, AEC-Q200 Grade 0, 0402; Manufacturer: Vishay-Dale; Power_W: 63mW; TempCo: 200 ppm/C; Value_Code: 47k0; Value: 47k; EIA_Code: E24; SizeX_mm: 1; SizeY_mm: 0.5; SizeZ_mm: 0.6; Value2: 0.063W; AEC Qualified: Y; VDC_V: 50V; AEC Category: Q200; AEC Grade: 0
SW1-SW3 = CMP-0008295-1: Switch Tactile N.O. SPST Round Button PC Pins 0.05A 50VDC 2.45N Thru-Hole; Manufacturer: E-Switch; Circuit: SPST-NO; SizeZ_mm: 13.25mm; VDC_V: 12V; AEC Qualified: No; Coil Resistance_ohm: 100mΩ; Contact Current Rating: 50mA; Electromechanical Life: 100000Cycles; Operating Force: 250gf
TP1 = CMP-0055058-1: PCB Pin, 0.46 Dia, Gold, TH; Manufacturer: Mill-Max; CNHeader: FALSE; Gender: Male; CompType: PCB Pin; Shrouded: N
U1 = CMP-0078033-1: Ultra-Low Power 1.65V to 5.5V Hall Effect Switch Sensor, DBZ0003A (SOT-23-3); Alternate Manufacturer: Texas Instruments; SizeAreaWB_mm2: 14; SizeZ_mm: 1.12; SizeX_mm: 2.5; SizeY_mm: 3; SizeArea_mm2: 7.5; CompType: IC; AEC Qualified: N; AEC Category: Q200
U2 = CMP-0034581-1: Manufacturer: Texas Instruments; SizeZ_mm: 1.6mm; Standoff Height: 0.05mm
U4 = CMP-0005381-2: 3V 8M-BIT SERIAL FLASH MEMORY WITH DUAL/QUAD SPI, SOIC-8; Manufacturer: Winbond; SizeZ_mm: 1.75; SizeX_mm: 5.99; SizeY_mm: 4.9; SizeArea_mm2: 29.351; SizeAreaWB_mm2: 55.131
Y1 = CMP-0085525-1: Crystal, 16.384 MHz, 50 ppm, 10 pF, SMD; Manufacturer: Epson; SizeArea_mm2: 8; SizeAreaWB_mm2: 14.7; SizeZ_mm: 0.7; Load Capacitance: 10 pF; AEC Qualified: N; Frequency Stability: 30 ppm; TaMax_C: 70°C; SizeY_mm: 3.2; Frequency Tolerance: 50 ppm; SizeX_mm: 2.5; AEC Category: Q200; TaMin_C: -20°C
Y2 = CMP-0004693-2: Crystal, 32.768 KHz, 12.5 pF, SMD; Manufacturer: Epson; TaMax_C: 85°C; TaMin_C: -40°C; U/M: EA

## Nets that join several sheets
DGND: TIDA-010940E3-Interfaces (6 pins), TIDA-010940E3-1P_ADS131M03 (16 pins), TIDA-010940E3-M0L228_80p (28 pins)
DVDD: TIDA-010940E3-Interfaces (C81.1 J3.2 U11.1 U11.7), TIDA-010940E3-1P_ADS131M03 (7 pins), TIDA-010940E3-M0L228_80p (21 pins)
ACT: TIDA-010940E3-Interfaces (J3.1), TIDA-010940E3-M0L228_80p (D1.1 R38.1 U2.31)
ADC_DIN: TIDA-010940E3-1P_ADS131M03 (U6.16), TIDA-010940E3-M0L228_80p (U2.58)
ADC_DOUT: TIDA-010940E3-1P_ADS131M03 (U6.15), TIDA-010940E3-M0L228_80p (U2.60)
ADC_SPI0_CS1: TIDA-010940E3-1P_ADS131M03 (U6.12), TIDA-010940E3-M0L228_80p (U2.76)
ADC_SPI0_SCLK: TIDA-010940E3-1P_ADS131M03 (U6.14), TIDA-010940E3-M0L228_80p (U2.59)
CLKIN: TIDA-010940E3-1P_ADS131M03 (U6.17), TIDA-010940E3-M0L228_80p (R27.2 U2.79)
~{DRDY}: TIDA-010940E3-1P_ADS131M03 (U6.13), TIDA-010940E3-M0L228_80p (U2.4)
M0_RX: TIDA-010940E3-Interfaces (Q1.3 R16.1 R18.1), TIDA-010940E3-M0L228_80p (U2.16)
M0_TX: TIDA-010940E3-Interfaces (D9.1 R36.1), TIDA-010940E3-M0L228_80p (U2.15)
M0_VCC_OPTO: TIDA-010940E3-Interfaces (R15.2 R16.2 R17.2), TIDA-010940E3-M0L228_80p (U2.32)
REACT: TIDA-010940E3-Interfaces (J12.1), TIDA-010940E3-M0L228_80p (D2.1 R37.1 U2.24)
~{SYNC}/~{RESET}: TIDA-010940E3-1P_ADS131M03 (U6.11), TIDA-010940E3-M0L228_80p (U2.5)
Serial_RE_DE: TIDA-010940E3-Interfaces (U11.3), TIDA-010940E3-M0L228_80p (U2.21)
Serial_RX: TIDA-010940E3-Interfaces (U11.5), TIDA-010940E3-M0L228_80p (U2.23)
Serial_TX: TIDA-010940E3-Interfaces (U11.4), TIDA-010940E3-M0L228_80p (U2.22)

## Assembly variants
001: not fitted C9 C68 C84 C85 D3 D4 D5 D6 D7 D8 D9 D10 D12 D13 D14 D15 D16 FID1 FID2 FID3 J5 J6 J7 J8 J10 J11 J20 R2 R15 R25 R31 R36 R37 R38 R52 R55 R146 R154 TP1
